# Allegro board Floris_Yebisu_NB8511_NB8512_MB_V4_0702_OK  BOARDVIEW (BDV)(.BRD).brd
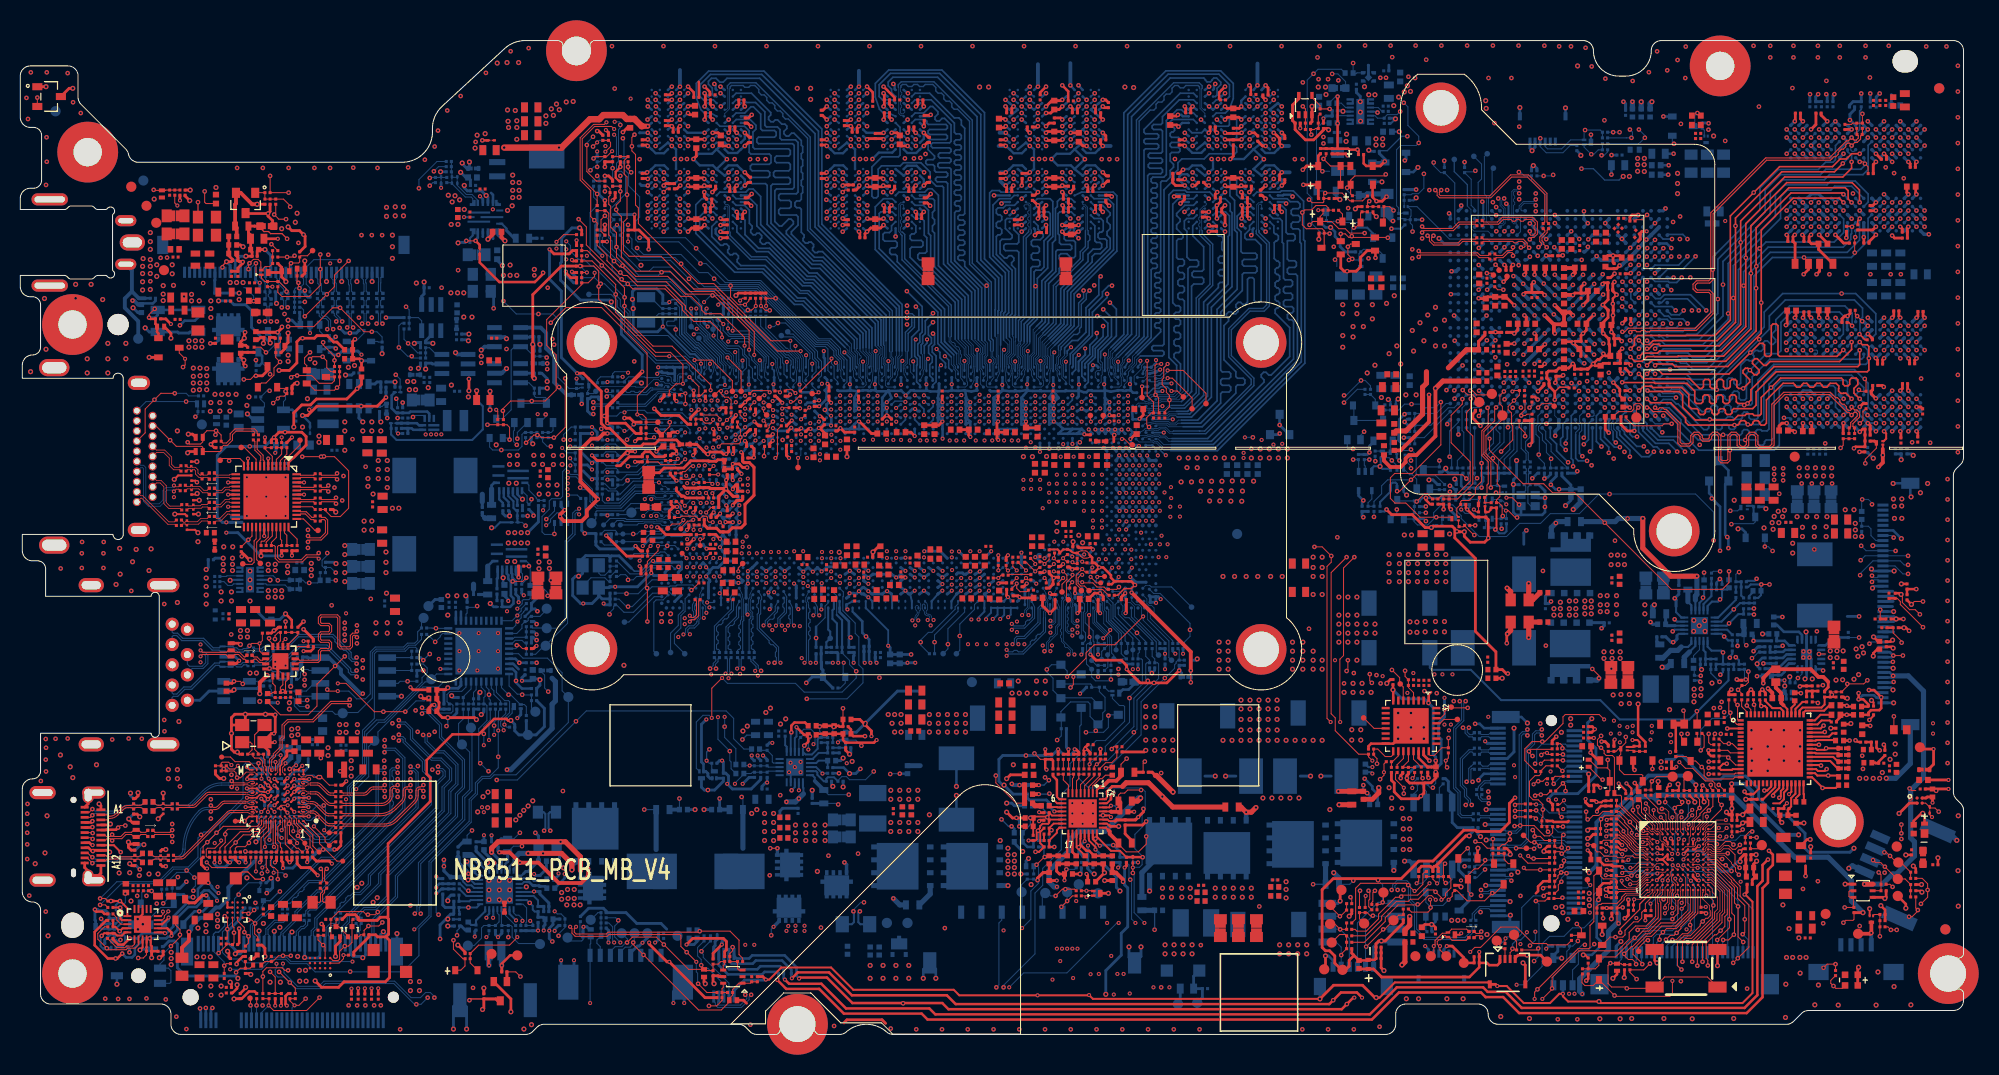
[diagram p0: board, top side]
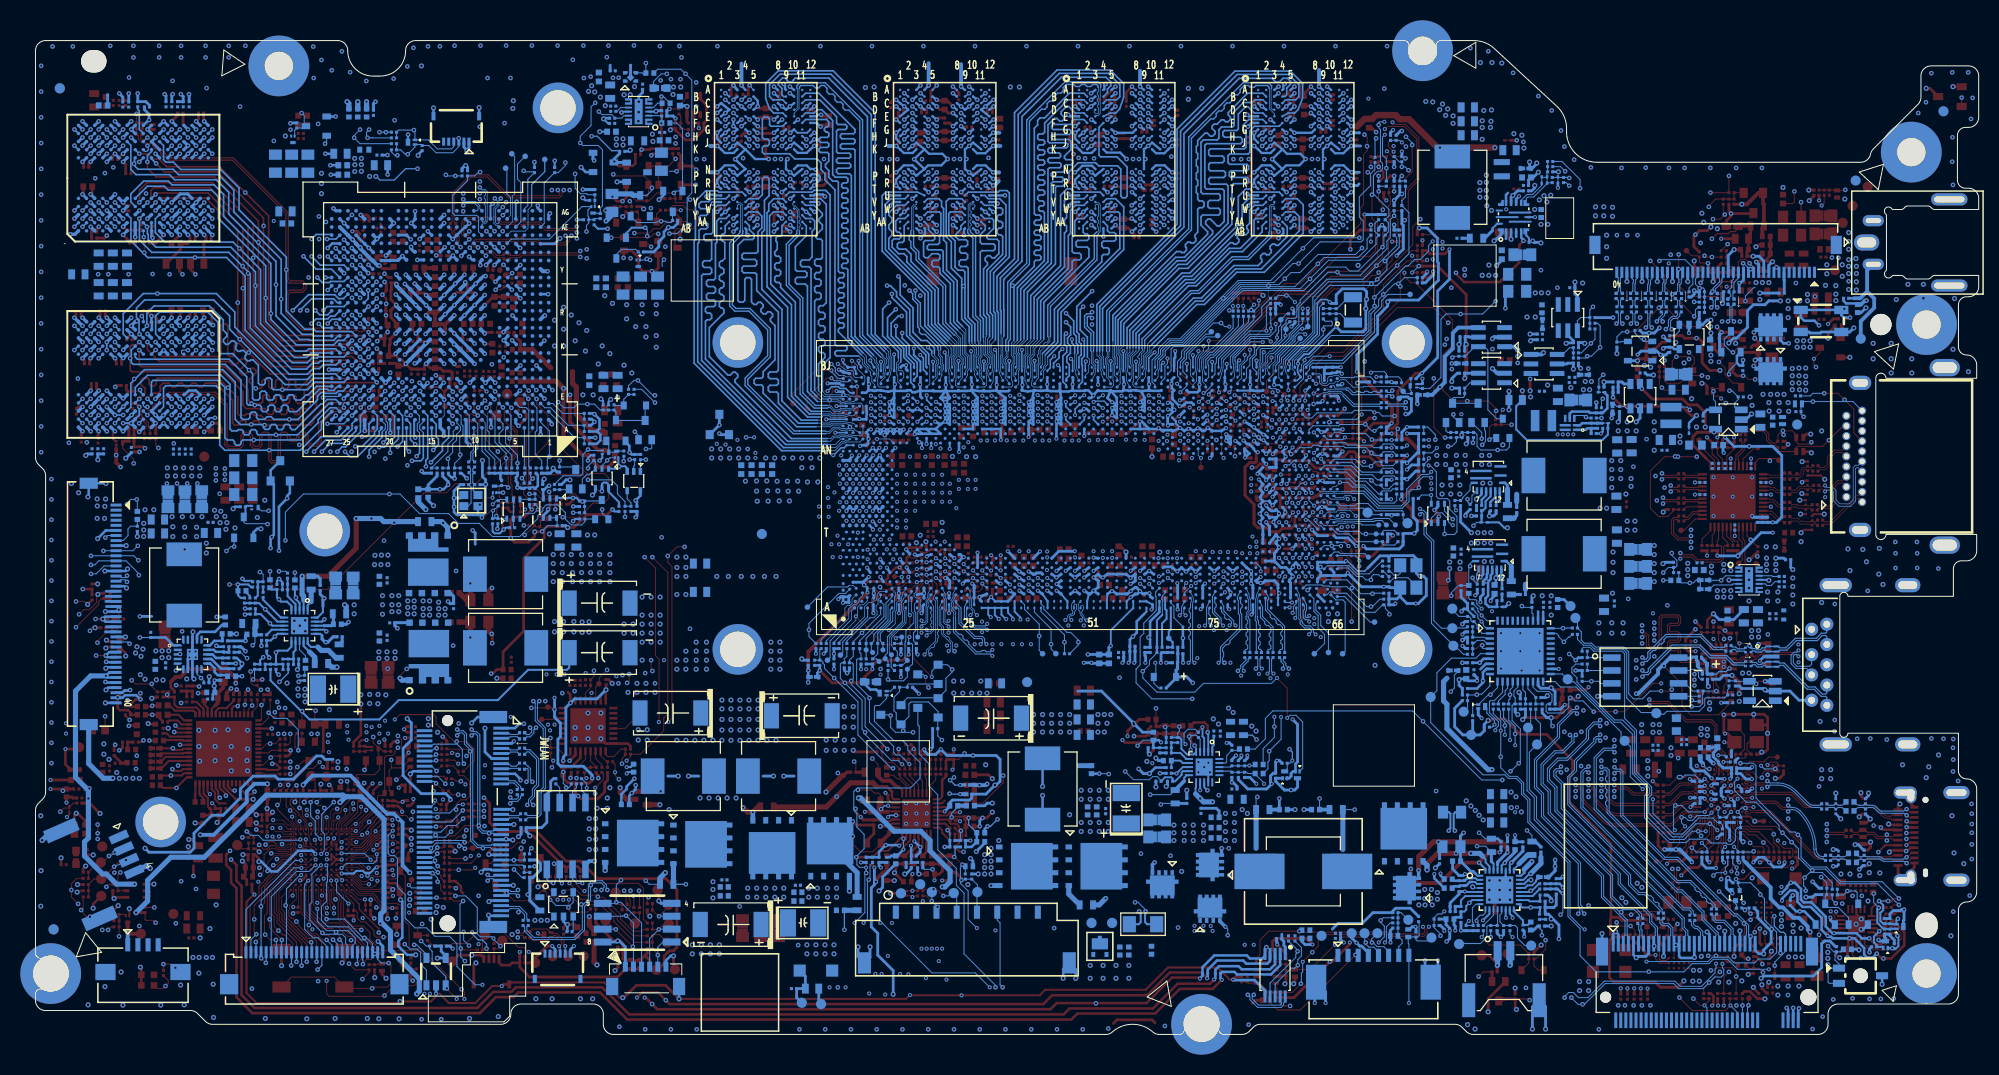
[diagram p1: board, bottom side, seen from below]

Outline 191.65 x 98 mm; copper layers: TOP, GND02, ART03, PWR04, ART05, ART06, GND07, BOTTOM. Coordinates in mm from the lower left corner of the outline.

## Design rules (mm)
constraint set DEFAULT: min track width 0.102
net group 10/10: nets VCC_VCCIN_SENSE_N VCC_VCCIN_SENSE_P
net group BB_TCP0_FLASH_CLK: nets BB_TCP0_FLASH_CLK BB_TCP0_FLASH_CLK_R
net group BB_TCP0_FLASH_CS_N: nets BB_TCP0_FLASH_CS_N BB_TCP0_FLASH_CS_N_R
net group BB_TCP0_FLASH_DI: nets BB_TCP0_FLASH_DI BB_TCP0_FLASH_DI_R
net group BB_TCP0_FLASH_DO: nets BB_TCP0_FLASH_DO BB_TCP0_FLASH_DO_R
net group BC_PROCHOT_N_PD: nets BC_PROCHOT_N_PD SRC_PS_FLT_N
net group BI_GATE: nets BI_GATE N40277712
net group CHG_PSYS: nets CHG_PSYS VR_PSYS
net group CHG_SCL: nets CHG_SCL SM_BAT_CLK
net group CHG_SDA: nets CHG_SDA SM_BAT_DATA
net group CHG_SR: nets CHG_SRN CHG_SRP
net group CNV_WR_CLK_CON_DN: nets CNV_WR_CLK_CON_DN CNV_WR_CLK_DN
net group CNV_WR_CLK_CON_DP: nets CNV_WR_CLK_CON_DP CNV_WR_CLK_DP
net group CNV_WR_D0_CON_DN: nets CNV_WR_D0_CON_DN CNV_WR_LANE0_DN
net group CNV_WR_D0_CON_DP: nets CNV_WR_D0_CON_DP CNV_WR_LANE0_DP
net group CNV_WR_D1_CON_DN: nets CNV_WR_D1_CON_DN CNV_WR_LANE1_DN
net group CNV_WR_D1_CON_DP: nets CNV_WR_D1_CON_DP CNV_WR_LANE1_DP
net group CNV_WT_CLK_DN: nets CNV_WT_CLK_DN CNV_WT_CLK_DN_R
net group CNV_WT_CLK_DP: nets CNV_WT_CLK_DP CNV_WT_CLK_DP_R
net group CNV_WT_LANE0_DN: nets CNV_WT_LANE0_DN CNV_WT_LANE0_DN_R
net group CNV_WT_LANE0_DP: nets CNV_WT_LANE0_DP CNV_WT_LANE0_DP_R
net group CNV_WT_LANE1_DN: nets CNV_WT_LANE1_DN CNV_WT_LANE1_DN_R
net group CNV_WT_LANE1_DP: nets CNV_WT_LANE1_DP CNV_WT_LANE1_DP_R
net group DDI1_HPD: nets DDI1_HPD DDI1_HPD_LV
net group DIFFPAIR333: nets PCIE_RCOMP_N PCIE_RCOMP_P
net group DIFFPAIR531: nets N33196202 N33196257
net group DIFFPAIR532: nets XTAL_IN XTAL_OUT
net group DIFFPAIR534: nets DDI1_DDC_SCL DDI1_DDC_SDA
net group DIFFPAIR541: nets VGA_SMB_CK2 VGA_SMB_DA2
net group DIFFPAIR542: nets SMB_EC_SCLK SMB_EC_SDATA
net group DIFFPAIR545: nets TOUCHPAD_I2C_CLK TOUCHPAD_I2C_SDA
net group DIFFPAIR559: nets FBA_CLK0 FBA_CLK0_N
net group DMIC1_CLK_AUDIO: nets DMIC1_CLK_AUDIO DMIC1_CLK_R
net group DMIC2_CLK_AUDIO: nets DMIC2_CLK_AUDIO DMIC2_CLK_R
net group EC ROM SPI-S-10: nets FLASH_SPI_HOLD_N_EC FLASH_SPI_WP_N_EC
net group EC_IMVP_PWRGD: nets EC_IMVP_PWRGD VR_READY
net group EC_SLP_S0_CS_N: nets EC_SLP_S0_CS_N HDMI_PDB_8409A
net group EDP_AUX_CONN_DN: nets EDP_AUX_C_DN EDP_AUX_CONN_DN
net group EDP_AUX_CONN_DP: nets EDP_AUX_C_DP EDP_AUX_CONN_DP
net group EDP_TX0_CONN_DN: nets EDP_TX0_C_DN EDP_TX0_CONN_DN
net group EDP_TX0_CONN_DP: nets EDP_TX0_C_DP EDP_TX0_CONN_DP
net group EDP_TX1_CONN_DN: nets EDP_TX1_C_DN EDP_TX1_CONN_DN
net group EDP_TX1_CONN_DP: nets EDP_TX1_C_DP EDP_TX1_CONN_DP
net group EDP_TX2_CONN_DN: nets EDP_TX2_C_DN EDP_TX2_CONN_DN
net group EDP_TX2_CONN_DP: nets EDP_TX2_C_DP EDP_TX2_CONN_DP
net group EDP_TX3_CONN_DN: nets EDP_TX3_C_DN EDP_TX3_CONN_DN
net group EDP_TX3_CONN_DP: nets EDP_TX3_C_DP EDP_TX3_CONN_DP
net group FLASH_SPI_IO2: nets FLASH_SPI_IO2 FLASH_SPI_IO2_IC
net group FLASH_SPI_IO3: nets FLASH_SPI_IO3 FLASH_SPI_IO3_IC
net group HDMI_CLK_DN: nets HDMI_CLK_CONN_DN HDMI_CLK_DN
net group HDMI_CLK_DP: nets HDMI_CLK_CONN_DP HDMI_CLK_DP
net group HDMI_DDC_SCL_8409A: nets HDMI_DDC_SCL HDMI_DDC_SCL_8409A
net group HDMI_DDC_SDA_8409A: nets HDMI_DDC_SDA HDMI_DDC_SDA_8409A
net group HDMI_TX0_DN: nets HDMI_TX0_CONN_DN HDMI_TX0_DN
net group HDMI_TX0_DP: nets HDMI_TX0_CONN_DP HDMI_TX0_DP
net group HDMI_TX1_DN: nets HDMI_TX1_CONN_DN HDMI_TX1_DN
net group HDMI_TX1_DP: nets HDMI_TX1_CONN_DP HDMI_TX1_DP
net group HDMI_TX2_DN: nets HDMI_TX2_CONN_DN HDMI_TX2_DN
net group HDMI_TX2_DP: nets HDMI_TX2_CONN_DP HDMI_TX2_DP
net group I2C_PD_SCL: nets I2C_PD_SCL TYPEC_PD_RETIMER_CLK
net group I2C_PD_SDA: nets I2C_PD_SDA TYPEC_PD_RETIMER_DAT
net group MIPI60_CPU_JTAG_TCLK: nets MIPI60_CPU_JTAG_TCLK MIPI60_PCH_JTAGX
net group MIPI60_CPU_JTAG_TDI: nets MIPI60_CPU_JTAG_TDI MIPI60_PCH_JTAG_TDI
net group MIPI60_CPU_JTAG_TDO: nets MIPI60_CPU_JTAG_TDO MIPI60_PCH_JTAG_TDO
net group MIPI60_CPU_JTAG_TMS: nets MIPI60_CPU_JTAG_TMS MIPI60_PCH_JTAG_TMS
net group MIPI60_CPU_JTAG_TRST_N: nets MIPI60_CPU_JTAG_TRST_N MIPI60_PCH_JTAG_TRST_N
net group PSI_VGA: nets PSI_VGA VGA_CORE_PSI
net group PWR_BUTTON_N_KB: nets PWR_BUTTON_N PWR_BUTTON_N_KB
net group SMB_TYPEC_SCLK: nets SMB_TYPEC_SCLK TYPEC_PD_SCLK
net group SMB_TYPEC_SDATA: nets SMB_TYPEC_SDATA TYPEC_PD_SDA
net group SSD_RST_N: nets PLT_RST_N_SSD SSD_RST_N
net group TCP0_ATEST_: nets TCP0_ATEST_N TCP0_ATEST_P
net group TCP0_SBU1: nets TCP0_SBU1 TCP0_SBU1_CONN
net group TCP0_SBU2: nets TCP0_SBU2 TCP0_SBU2_CONN
net group TCP0_TX0_C_DN: nets TCP0_TX0_C_DN TCP0_TX0_DN
net group TCP0_TX0_C_DP: nets TCP0_TX0_C_DP TCP0_TX0_DP
net group TCP0_TX1_C_DN: nets TCP0_TX1_C_DN TCP0_TX1_DN
net group TCP0_TX1_C_DP: nets TCP0_TX1_C_DP TCP0_TX1_DP
net group TCP0_TXRX0_C_DN: nets TCP0_TXRX0_C_DN TCP0_TXRX0_DN
net group TCP0_TXRX0_C_DP: nets TCP0_TXRX0_C_DP TCP0_TXRX0_DP
net group TCP0_TXRX1_C_DN: nets TCP0_TXRX1_C_DN TCP0_TXRX1_DN
net group TCP0_TXRX1_C_DP: nets TCP0_TXRX1_C_DP TCP0_TXRX1_DP
net group TCRCOMP_D: nets TCRCOMP_DN TCRCOMP_DP
net group TYPE-C-85OHM-S-12-S-15: nets TCP0_AUX_DN TCP0_AUX_DP
net group TYPEC_PD_CSN: nets N41385208 TYPEC_PD_CSN
net group TYPEC_PD_CSP: nets N41385128 TYPEC_PD_CSP
net group TYPEC_PD_SOC_CLK: nets TYPEC_PD_SOC_CLK TYPEC_PD_SOC_CLK_R
net group TYPEC_PD_SOC_DAT: nets TYPEC_PD_SOC_DAT TYPEC_PD_SOC_DAT_R
net group USB2_P1_DN_R: nets USB2_P1_DN_R USBP6_DN_CONN
net group USB2_P1_DP_R: nets USB2_P1_DP_R USBP6_DP_CONN
net group USB2_P3_TYPEC_DN: nets USB2_P3_TYPEC_DN USB2_P3_TYPEC_DN_CON
net group USB2_P3_TYPEC_DP: nets USB2_P3_TYPEC_DP USB2_P3_TYPEC_DP_CON
net group VCCIN_AUX_IS: nets VCCIN_AUX_ISN VCCIN_AUX_ISP
net group VCCIN_ISEN1: nets VCCIN_ISEN1N VCCIN_ISEN1P
net group VCCIN_ISEN2: nets VCCIN_ISEN2N VCCIN_ISEN2P
net group VCCIN_VIDSCK: nets VCCIN_VIDSCK VCCIN_VIDSCK_R
net group VCCIN_VIDSOUT: nets VCCIN_VIDSOUT VCCIN_VIDSOUT_R
net group VCCSENSE_VGA: nets VCCSENSE_VGA VGA_CORE_VSNS
net group VSSSENSE_VGA: nets VGA_CORE_RGND VSSSENSE_VGA
net group 3P3VA_EN: nets 3P3VA_EN EC_OVT_N EC_WRST_N N39502644 N39574885
net group +VCC3V3_SX_TCP1: nets N40898959
net group BB_TCP0_RESET_N: nets BB_TCP0_RESET_N SLP_S5_N TCP0_RESET_N
net group BB_TCP1_LS_EN: nets BB_TCP1_LS_EN BB_TCP1_LS_EN_R UART_TX_P1
net group CLK-S-15: nets PCIE_SSD_CLKREQ1 PCIE_WLAN_CLK_REQ_N PCIE_WLAN_CLK_REQ_N_C
net group DDI-85OHM-S-12: nets DDI1_TX0_DN DDI1_TX0_DP DDI1_TX1_DN DDI1_TX1_DP DDI1_TX2_DN DDI1_TX2_DP DDI1_TX3_DN DDI1_TX3_DP HDMI_CLK_LV_DN HDMI_CLK_LV_DP HDMI_TX0_LV_DN HDMI_TX0_LV_DP HDMI_TX1_LV_DN HDMI_TX1_LV_DP HDMI_TX2_LV_DN HDMI_TX2_LV_DP
net group DDR4-CLKA-75OHM-S-12-S-20: nets M_A_CK_DDR0_DN M_A_CK_DDR0_DP M_A_CK_DDR1_DN M_A_CK_DDR1_DP
net group DDR4-CLKB-75OHM-S-12-S-20: nets M_B_CK_DDR0_DN M_B_CK_DDR0_DP M_B_CK_DDR1_DN M_B_CK_DDR1_DP
net group DDR4-CMDA-40OHM-S-10-S-20: nets M_A_LP4_CAA0 M_A_LP4_CAA1 M_A_LP4_CAA2 M_A_LP4_CAA3 M_A_LP4_CAA4 M_A_LP4_CAA5 M_A_LP4_CAB0 M_A_LP4_CAB1 M_A_LP4_CAB2 M_A_LP4_CAB3 M_A_LP4_CAB4 M_A_LP4_CAB5 M_A_LP4_CKE_A0 M_A_LP4_CKE_A1 M_A_LP4_CKE_B0 M_A_LP4_CKE_B1 M_A_LP4_CS_A_R0_N M_A_LP4_CS_A_R1_N M_A_LP4_CS_B_R0_N M_A_LP4_CS_B_R1_N
net group DDR4-CMDB-40OHM-S-10-S-15: nets M_B_LP4_CAA0 M_B_LP4_CAA1 M_B_LP4_CAA2 M_B_LP4_CAA3 M_B_LP4_CAA4 M_B_LP4_CAA5 M_B_LP4_CAB0 M_B_LP4_CAB1 M_B_LP4_CAB2 M_B_LP4_CAB3 M_B_LP4_CAB4 M_B_LP4_CAB5 M_B_LP4_CKE_A0 M_B_LP4_CKE_A1 M_B_LP4_CKE_B0 M_B_LP4_CKE_B1 M_B_LP4_CS_A_R0_N M_B_LP4_CS_A_R1_N M_B_LP4_CS_B_R0_N M_B_LP4_CS_B_R1_N
net group DDR4-DATA0-40OHM-S-6-S-15: nets M_A_DQ_0[0] M_A_DQ_0[1] M_A_DQ_0[2] M_A_DQ_0[3] M_A_DQ_0[4] M_A_DQ_0[5] M_A_DQ_0[6] M_A_DQ_0[7] M_A_DQS_0_DN M_A_DQS_0_DP
net group DDR4-DATA1-40OHM-S-6-S-15: nets M_A_DQ_1[0] M_A_DQ_1[1] M_A_DQ_1[2] M_A_DQ_1[3] M_A_DQ_1[4] M_A_DQ_1[5] M_A_DQ_1[6] M_A_DQ_1[7] M_A_DQS_1_DN M_A_DQS_1_DP
net group DDR4-DATA2-40OHM-S-6-S-15: nets M_A_DQ_2[0] M_A_DQ_2[1] M_A_DQ_2[2] M_A_DQ_2[3] M_A_DQ_2[4] M_A_DQ_2[5] M_A_DQ_2[6] M_A_DQ_2[7] M_A_DQS_2_DN M_A_DQS_2_DP
net group DDR4-DATA3-40OHM-S-6-S-15: nets M_A_DQ_3[0] M_A_DQ_3[1] M_A_DQ_3[2] M_A_DQ_3[3] M_A_DQ_3[4] M_A_DQ_3[5] M_A_DQ_3[6] M_A_DQ_3[7] M_A_DQS_3_DN M_A_DQS_3_DP
net group DDR4-DATA4-40OHM-S-6-S-15: nets M_A_DQ_4[0] M_A_DQ_4[1] M_A_DQ_4[2] M_A_DQ_4[3] M_A_DQ_4[4] M_A_DQ_4[5] M_A_DQ_4[6] M_A_DQ_4[7] M_A_DQS_4_DN M_A_DQS_4_DP
net group DDR4-DATA5-40OHM-S-6-S-15: nets M_A_DQ_5[0] M_A_DQ_5[1] M_A_DQ_5[2] M_A_DQ_5[3] M_A_DQ_5[4] M_A_DQ_5[5] M_A_DQ_5[6] M_A_DQ_5[7] M_A_DQS_5_DN M_A_DQS_5_DP
net group DDR4-DATA6-40OHM-S-6-S-15: nets M_A_DQ_6[0] M_A_DQ_6[1] M_A_DQ_6[2] M_A_DQ_6[3] M_A_DQ_6[4] M_A_DQ_6[5] M_A_DQ_6[6] M_A_DQ_6[7] M_A_DQS_6_DN M_A_DQS_6_DP
net group DDR4-DATA7-40OHM-S-6-S-15: nets M_A_DQ_7[0] M_A_DQ_7[1] M_A_DQ_7[2] M_A_DQ_7[3] M_A_DQ_7[4] M_A_DQ_7[5] M_A_DQ_7[6] M_A_DQ_7[7] M_A_DQS_7_DN M_A_DQS_7_DP
net group DDR4-DATAB0-40OHM-S-6-S-15: nets M_B_DQ_0[0] M_B_DQ_0[1] M_B_DQ_0[2] M_B_DQ_0[3] M_B_DQ_0[4] M_B_DQ_0[5] M_B_DQ_0[6] M_B_DQ_0[7] M_B_DQS_0_DN M_B_DQS_0_DP
net group DDR4-DATAB1-40OHM-S-6-S-15: nets M_B_DQ_1[0] M_B_DQ_1[1] M_B_DQ_1[2] M_B_DQ_1[3] M_B_DQ_1[4] M_B_DQ_1[5] M_B_DQ_1[6] M_B_DQ_1[7] M_B_DQS_1_DN M_B_DQS_1_DP
net group DDR4-DATAB2-40OHM-S-6-S-15: nets M_B_DQ_2[0] M_B_DQ_2[1] M_B_DQ_2[2] M_B_DQ_2[3] M_B_DQ_2[4] M_B_DQ_2[5] M_B_DQ_2[6] M_B_DQ_2[7] M_B_DQS_2_DN M_B_DQS_2_DP
net group DDR4-DATAB3-40OHM-S-6-S-15: nets M_B_DQ_3[0] M_B_DQ_3[1] M_B_DQ_3[2] M_B_DQ_3[3] M_B_DQ_3[4] M_B_DQ_3[5] M_B_DQ_3[6] M_B_DQ_3[7] M_B_DQS_3_DN M_B_DQS_3_DP
net group DDR4-DATAB4-40OHM-S-6-S-15: nets M_B_DQ_4[0] M_B_DQ_4[1] M_B_DQ_4[2] M_B_DQ_4[3] M_B_DQ_4[4] M_B_DQ_4[5] M_B_DQ_4[6] M_B_DQ_4[7] M_B_DQS_4_DN M_B_DQS_4_DP
net group DDR4-DATAB5-40OHM-S-6-S-15: nets M_B_DQ_5[0] M_B_DQ_5[1] M_B_DQ_5[2] M_B_DQ_5[3] M_B_DQ_5[4] M_B_DQ_5[5] M_B_DQ_5[6] M_B_DQ_5[7] M_B_DQS_5_DN M_B_DQS_5_DP
net group DDR4-DATAB6-40OHM-S-6-S-15: nets M_B_DQ_6[0] M_B_DQ_6[1] M_B_DQ_6[2] M_B_DQ_6[3] M_B_DQ_6[4] M_B_DQ_6[5] M_B_DQ_6[6] M_B_DQ_6[7] M_B_DQS_6_DN M_B_DQS_6_DP
net group DDR4-DATAB7-40OHM-S-6-S-15: nets M_B_DQ_7[0] M_B_DQ_7[1] M_B_DQ_7[2] M_B_DQ_7[3] M_B_DQ_7[4] M_B_DQ_7[5] M_B_DQ_7[6] M_B_DQ_7[7] M_B_DQS_7_DN M_B_DQS_7_DP
net group DDR-FBA_WCK-80OHM-S-12: nets FBA_WCK01 FBA_WCK01_N FBA_WCK23 FBA_WCK23_N FBA_WCK45 FBA_WCK45_N FBA_WCK67 FBA_WCK67_N
net group DIFF-I2C: nets DMIC1_CLK DMIC1_DATA DMIC1_DATA_AUDIO N26347975 N26347977 PCH_DMIC1_CLK0 PCH_DMIC1_DATA0 PCH_SMB1_CLK PCH_SMB1_DATA SM_BATT_SCL SM_BATT_SDA TOUCHPAD_I2C_CLK_C TOUCHPAD_I2C_SDA_C
net group EC SPI-S-10: nets ESPI_CLK ESPI_CLK_EC ESPI_CS_N ESPI_IO0 ESPI_IO0_EC ESPI_IO1 ESPI_IO1_EC ESPI_IO2 ESPI_IO2_EC ESPI_IO3 ESPI_IO3_EC ESPI_RESET
net group EC_FLASH_SPI_CLK: nets EC_FLASH_SPI_CLK FLASH_SPI_CLK FLASH_SPI_CLK_EC FLASH_SPI_CLK_IC
net group EC_FLASH_SPI_CS0_N: nets EC_FLASH_SPI_CS0_N FLASH_SPI_CS0_N FLASH_SPI_CS0_N_EC FLASH_SPI_CS0_N_IC
net group EC_FLASH_SPI_MISO: nets EC_FLASH_SPI_MISO FLASH_SPI_MISO FLASH_SPI_MISO_EC FLASH_SPI_MISO_IC
net group EC_FLASH_SPI_MOSI: nets EC_FLASH_SPI_MOSI FLASH_SPI_MOSI FLASH_SPI_MOSI_EC FLASH_SPI_MOSI_IC
net group EC_SLP_SX_N: nets EC_SLP_SX_N N40993990 N42165106
net group EDP-85OHM-S-12: nets EDP_AUX_SOC_DN EDP_AUX_SOC_DP EDP_TX0_SOC_DN EDP_TX0_SOC_DP EDP_TX1_SOC_DN EDP_TX1_SOC_DP EDP_TX2_SOC_DN EDP_TX2_SOC_DP EDP_TX3_SOC_DN EDP_TX3_SOC_DP
net group GDRR5_ADD_H-40OHM-S-13.5: nets FBA_A0_A10_H FBA_A1_A9_H FBA_A2_BA0_H FBA_A3_BA3_H FBA_A4_BA2_H FBA_A5_BA1_H FBA_A6_A11_H FBA_A7_A8_H FBA_A12_RFU_H
net group GDRR5_ADD_L-40OHM-S-13.5: nets FBA_A0_A10_L FBA_A1_A9_L FBA_A3_BA3_L FBA_A4_BA2_L FBA_A5_BA1_L FBA_A6_A11_L FBA_A7_A8_L FBA_A12_RFU_L
net group GDRR5_CMD_H-40OHM-S-13.5: nets FBA_ABI_H FBA_CAS_H FBA_CS_H FBA_RAS_H FBA_WE_H
net group GDRR5_CMD_L-40OHM-S-13.5: nets FBA_ABI_L FBA_CAS_L FBA_CS_L FBA_RAS_L FBA_WE_L
net group GDRR5_CONTROL-40OHM-S-13.5: nets FBA_RST_L
net group HDMI-85OHM-S-12: nets HDMI_CLK_CONN_DN_R HDMI_CLK_CONN_DP_R HDMI_TX0_CONN_DN_R HDMI_TX0_CONN_DP_R HDMI_TX1_CONN_DN_R HDMI_TX1_CONN_DP_R HDMI_TX2_CONN_DN_R HDMI_TX2_CONN_DP_R
net group PCIE-85OHM-S-12: nets PCIE13_CRX_DTX_N PCIE13_CRX_DTX_P PCIE13_CTX_DRX_N PCIE13_CTX_DRX_N_C PCIE13_CTX_DRX_P PCIE13_CTX_DRX_P_C PCIE14_CRX_DTX_N PCIE14_CRX_DTX_P PCIE14_CTX_DRX_N PCIE14_CTX_DRX_N_C PCIE14_CTX_DRX_P PCIE14_CTX_DRX_P_C PCIE15_CRX_DTX_N PCIE15_CRX_DTX_P PCIE15_CTX_DRX_N PCIE15_CTX_DRX_N_C PCIE15_CTX_DRX_P PCIE15_CTX_DRX_P_C PCIE16_SATA_CRX_DTX_N PCIE16_SATA_CRX_DTX_P PCIE16_SATA_CTX_DRX_N PCIE16_SATA_CTX_DRX_N_C PCIE16_SATA_CTX_DRX_P PCIE16_SATA_CTX_DRX_P_C PCIE_CRX_C_GTX_N0 PCIE_CRX_C_GTX_N1 PCIE_CRX_C_GTX_N2 PCIE_CRX_C_GTX_N3 PCIE_CRX_C_GTX_P0 PCIE_CRX_C_GTX_P1 PCIE_CRX_C_GTX_P2 PCIE_CRX_C_GTX_P3 PCIE_CRX_GTX_N0 PCIE_CRX_GTX_N1 PCIE_CRX_GTX_N2 PCIE_CRX_GTX_N3 PCIE_CRX_GTX_P0 PCIE_CRX_GTX_P1 PCIE_CRX_GTX_P2 PCIE_CRX_GTX_P3 PCIE_CTX_GRX_N0 PCIE_CTX_GRX_N0_C PCIE_CTX_GRX_N1 PCIE_CTX_GRX_N1_C PCIE_CTX_GRX_N2 PCIE_CTX_GRX_N2_C PCIE_CTX_GRX_N3 PCIE_CTX_GRX_N3_C PCIE_CTX_GRX_P0 PCIE_CTX_GRX_P0_C PCIE_CTX_GRX_P1 PCIE_CTX_GRX_P1_C PCIE_CTX_GRX_P2 PCIE_CTX_GRX_P2_C PCIE_CTX_GRX_P3 PCIE_CTX_GRX_P3_C PCIE_WLAN_RX_DN PCIE_WLAN_RX_DP PCIE_WLAN_TX_DN PCIE_WLAN_TX_DN_C PCIE_WLAN_TX_DP PCIE_WLAN_TX_DP_C
net group PCIE-CLK-85OHM-S-12-S-15: nets PCIE_REFCLK_GFX_DN PCIE_REFCLK_GFX_DP PCIE_REFCLK_SSD_DN PCIE_REFCLK_SSD_DP PCIE_REFCLK_WLAN_DN PCIE_REFCLK_WLAN_DP
net group PLT_RST_N: nets PLT_RST_N TCP_RETIMER_PERST_N TCP_RETIMER_PERST_N_R
net group PWR: nets 1V8MAINEN_33 +V1P8_AON_EN_N +V3P3_CAM_CONN +V3P3_MIC +V3P3A_SPI_FLASH +V3P3A_VSYS_PD +VBUS_WC +VCC0P9_LVR_TCP1 +VCC3V3A_S0_TCP1 +VCCDSW_1P05 +VCCRTC CHG_COMP1 CHG_COMP1_R CHG_ILIM_HIZ CHG_REGN CHG_SNB2 CHG_VBUS CHG_VDDA CPU_POPI_RCOMP GPPC_B2_VRALERT_N N28124431 N29343591 N32026426 N32026428 N32028000 N32264097 N33504961 N38294628 N38297214 N39869300 N40407372 N40407375 N41030628 N41496684 V1P8A_EN V1P8A_FB V1P8A_FB_R V5P0A_BST_R V5P0A_FB V5P0A_FF V5P0A_FF_R V5P0A_LDO V5P0A_VCC VCCIN_AUX_VCCSENSE VCCIN_AUX_VSSSENSE VCCIN_BOOT1 VCCIN_BOOT1_R VCCIN_BOOT2 VCCIN_BOOT2_R VCCIN_LGATE1 VCCIN_LGATE2 VCCIN_PH1_SNUB VCCIN_PVCC VCCIN_UGATE1 VCCIN_UGATE1_R VCCIN_UGATE2 VCCIN_VREF VGA_CORE_UG1
net group RETIMER_FORCE_PWR: nets RETIMER_FORCE_PWR TC_RETIMER_FORCE_PWR UART_RX_P1
net group RT_TCP0_I2C0_SCL: nets RT_TCP0_I2C0_SCL SMBUS_CLK0 TCP_SMBUS_SCL
net group RT_TCP0_I2C0_SDA: nets RT_TCP0_I2C0_SDA SMBUS_DAT0 TCP_SMBUS_SDA
net group S-10-S-15: nets CNV_BRI_DT CNV_BRI_DT_SOC CNV_BRI_RSP CNV_BRI_RSP_SOC CNV_RGI_DT CNV_RGI_DT_SOC CNV_RGI_RSP CNV_RGI_RSP_SOC
net group S-12: nets CATERR_SOC_N CPU_PROCHOT_EC DSW_PWROK H_VCCST_PWRGD N38298094 PCH_PWROK PECI_EC PECI_SOC PLT_RST_SOC_N PM_SYSRST_N PROCHOT_EC_N PROCHOT_SOC_N PROCPWRGD RSMRST_N_EC SYS_PWROK TBT_LSX0_RXD TBT_LSX0_TXD THERMTRIP_SOC_N VCCST_OVERRIDE VCCSTPWRGOOD_TCSS
net group SNK_PS_ACK: nets SNK_PS_ACK SRC_PS_FO SRC_PS_FO_OVP_TRIP
net group TCP0_CC1_CONN: nets N40901169 TCP0_CC1_CONN TCP0_CC1_PD
net group TCP0_CC2_CONN: nets N40901167 TCP0_CC2_CONN TCP0_CC2_PD
net group TCP0_RT_TX0_DN: nets TCP0_RT_TX0_DN TCP0_RT_TX0_DN_C TCP0_RT_TX0_DN_CONN
net group TCP0_RT_TX0_DP: nets TCP0_RT_TX0_DP TCP0_RT_TX0_DP_C TCP0_RT_TX0_DP_CONN
net group TCP0_RT_TX1_DN: nets TCP0_RT_TX1_DN TCP0_RT_TX1_DN_C TCP0_RT_TX1_DN_CONN
net group TCP0_RT_TX1_DP: nets TCP0_RT_TX1_DP TCP0_RT_TX1_DP_C TCP0_RT_TX1_DP_CONN
net group TCP0_RT_TXRX0_DN: nets TCP0_RT_TXRX0_DN TCP0_RT_TXRX0_DN_C TCP0_RT_TXRX0_DN_CONN
net group TCP0_RT_TXRX0_DP: nets TCP0_RT_TXRX0_DP TCP0_RT_TXRX0_DP_C TCP0_RT_TXRX0_DP_CONN
net group TCP0_RT_TXRX1_DN: nets TCP0_RT_TXRX1_DN TCP0_RT_TXRX1_DN_C TCP0_RT_TXRX1_DN_CONN
net group TCP0_RT_TXRX1_DP: nets TCP0_RT_TXRX1_DP TCP0_RT_TXRX1_DP_C TCP0_RT_TXRX1_DP_CONN
net group TPM SPI: nets FLASH_SPI_CLK_TPM FLASH_SPI_CS2_N FLASH_SPI_CS2_N_TPM FLASH_SPI_MISO_TPM FLASH_SPI_MOSI_TPM
net group USB2-85OHM-S-12: nets CAM_USB_N_CONN_R CAM_USB_P_CONN_R USB2_P1_DN USB2_P1_DP USB2_P4_DN USB2_P4_DP USB2_P5_DN_FP USB2_P5_DP_FP USB2_P5_FP_DN USB2_P5_FP_DP USB2_P9_TS_DN USB2_P9_TS_DN_R USB2_P9_TS_DP USB2_P9_TS_DP_R USB2_P10_BT_DN USB2_P10_BT_DN_WIFI USB2_P10_BT_DP USB2_P10_BT_DP_WIFI USB_P7_CAM_N USB_P7_CAM_P
net group USB3-80MIL-18-S-20: nets USB3_P1_RX_DN USB3_P1_RX_DP USB3_P1_TX_DN USB3_P1_TX_DN_C USB3_P1_TX_DP USB3_P1_TX_DP_C USB3_RXN1_R USB3_RXP1_R USB3_TXN1_R USB3_TXP1_R
net group VCCIN_VIDALERT_N: nets VCCIN_VIDALERT_N VCCIN_VIDALERT_N_R VR_SVID_ALERT_N

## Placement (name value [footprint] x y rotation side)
+1.35VGS1  C40_1  [CMP_40]  175 56.97 0 top
+V1P8SX  40MIL  [CMP_40]  187.35 28.32 0 top
+V5P0SX_HDMI_F  C40_1  [CMP_40]  17.91 60.14 180 bottom
+VCCIN1  C40_1  [CMP_40]  120.01 49.35 90 bottom
+VCCIN_AUX1  C40_1  [CMP_40]  93.85 34.74 180 bottom
C8  C0201C0G101J250NTA+C0201C0G101J250NJA~~GRM0335C1E101JD01D~~CC0201JRNPO8BN101  [C0201]  14.73 83 270 top
C9  C0402X5R475M6R3NTC~~JMK105BBJ475MV-F+JDK105ABJ475MV~~CC0402MRX5R5BB475~~CL05A475MQ5NRNC~~GRM155R60J475ME87D  [C0402_0D65]  138.22 10.13 270 top
C10  C0201X5R104M6R3NTA~~0201X104M6R3NT  [C0201]  139.57 10.16 90 top
CA8  C0402X5R106M6R3NTC~~CL05A106MQ5NUNC~~GRM155R60J106ME44~~JMK105CBJ106MV-F  [C0402_0D8]  173.23 33.17 180 top
CA11  CL10A226MQ8NRNC~~GRM188R60J226MEA0D~~JDK107BBJ226MA-T~~CC0603MRX5R5BB226  [C0603_L]  175.61 17.96 90 top
CA12  C0201X5R104K6R3NTA+C0201X5R104K6R3NJA~~GRM033R60J104KE19D~~CC0201KRX5R5BB104  [C0201]  176.58 17.65 90 top
CA13  CL10A226MQ8NRNC~~GRM188R60J226MEA0D~~JDK107BBJ226MA-T~~CC0603MRX5R5BB226  [C0603_L]  171.24 22.27 180 top
CA14  C0201X5R104K6R3NTA+C0201X5R104K6R3NJA~~GRM033R60J104KE19D~~CC0201KRX5R5BB104  [C0201]  171.55 23.19 180 top
CA15  C0201X5R104K6R3NTA+C0201X5R104K6R3NJA~~GRM033R60J104KE19D~~CC0201KRX5R5BB104  [C0201]  176.17 33.04 90 top
CA16  C0201C0G101J250NTA+C0201C0G101J250NJA~~GRM0335C1E101JD01D~~CC0201JRNPO8BN101  [C0201]  176.73 34.11 90 top
CA17  C0603X5R106M6R3NTK~~CL10A106MQ8NNNC~~GRM188R60J106ME47D~~JMK107BJ106MA-T  [C0603_L]  171.24 20.95 180 top
CA18  C0201X5R104K6R3NTA+C0201X5R104K6R3NJA~~GRM033R60J104KE19D~~CC0201KRX5R5BB104  [C0201]  173.12 22.27 0 top
CA23  C0201C0G2R0C250NTA~~GRM0335C1E2R0CD01D~~CC0201CRNPO9BN2R0  [C0201]  169.8 34.67 90 top
CA24  C0201C0G100J250NTA~~GRM0335C1E100JA01D~~CC0201JRNPO8BN100  [C0201]  170.38 33.25 90 top
CA25  C0201C0G100J250NTA~~GRM0335C1E100JA01D~~CC0201JRNPO8BN100  [C0201]  169.11 33.25 90 top
CA26  C0201C0G100J250NTA~~GRM0335C1E100JA01D~~CC0201JRNPO8BN100  [C0201]  167.28 27.45 180 top
CA27  C0402X5R106M6R3NTC~~CL05A106MQ5NUNC~~GRM155R60J106ME44~~JMK105CBJ106MV-F  [C0402_0D8]  166.42 31.11 90 top
CA28  C0201X5R104K6R3NTA+C0201X5R104K6R3NJA~~GRM033R60J104KE19D~~CC0201KRX5R5BB104  [C0201]  170.69 23.44 270 top
CA31  CC0201JRNPO9BN220~~C0201C0G220J500NTA  [C0201]  170.94 33.25 90 top
CA32  C0402X5R106M6R3NTC~~CL05A106MQ5NUNC~~GRM155R60J106ME44~~JMK105CBJ106MV-F  [C0402_0D8]  181.66 30.05 90 top
CA34  GRM155R60J225KE95~~CL05A225KQ5NNNC  [C0402]  167.33 31.11 90 top
CA35  C0201X5R104K6R3NTA+C0201X5R104K6R3NJA~~GRM033R60J104KE19D~~CC0201KRX5R5BB104  [C0201]  184.35 26.24 270 top
CA36  C0201X5R104K6R3NTA+C0201X5R104K6R3NJA~~GRM033R60J104KE19D~~CC0201KRX5R5BB104  [C0201]  174.42 33.07 180 bottom
CA37  C0201X5R104K6R3NTA+C0201X5R104K6R3NJA~~GRM033R60J104KE19D~~CC0201KRX5R5BB104  [C0201]  184.02 38.48 90 top
CA38  C0201X7R221K500NTA~~GRM033R71H221KA12D~~CC0201KRX7R9BB221  [C0201]  184.3 43.25 90 top
CA56  GRM155R60J225KE95~~CL05A225KQ5NNNC  [C0402]  179.83 30.2 90 top
CA57  C0201X5R104K6R3NTA+C0201X5R104K6R3NJA~~GRM033R60J104KE19D~~CC0201KRX5R5BB104  [C0201]  179.07 29.94 90 top
CA58  GRM155R60J225KE95~~CL05A225KQ5NNNC  [C0402]  179.73 25.4 0 top
CA59  GRM155R60J225KE95~~CL05A225KQ5NNNC  [C0402]  179.73 24.58 0 top
CA60  GRM155R60J225KE95~~CL05A225KQ5NNNC  [C0402]  175.51 22.93 0 top
CA61  GRM155R60J225KE95~~CL05A225KQ5NNNC  [C0402]  173.94 21.61 180 top
CA62  C0201X5R104K6R3NTA+C0201X5R104K6R3NJA~~GRM033R60J104KE19D~~CC0201KRX5R5BB104  [C0201]  174.19 22.27 180 top
CA63  C0201C0G100J250NTA~~GRM0335C1E100JA01D~~CC0201JRNPO8BN100  [C0201]  167.28 28.01 180 top
CA64  C0201X5R104K6R3NTA+C0201X5R104K6R3NJA~~GRM033R60J104KE19D~~CC0201KRX5R5BB104  [C0201]  168.5 33.25 90 top
CA65  C0201X5R104K6R3NTA+C0201X5R104K6R3NJA~~GRM033R60J104KE19D~~CC0201KRX5R5BB104  [C0201]  171.55 33.25 90 top
CA66  C0201X5R104K6R3NTA+C0201X5R104K6R3NJA~~GRM033R60J104KE19D~~CC0201KRX5R5BB104  [C0201]  168.04 31.01 90 top
CA67  C0201X5R104K6R3NTA+C0201X5R104K6R3NJA~~GRM033R60J104KE19D~~CC0201KRX5R5BB104  [C0201]  167.28 26.29 180 top
CA68  GRM155R60J225KE95~~CL05A225KQ5NNNC  [C0402]  175 33.3 90 top
CA69  GRM155R60J225KE95~~CL05A225KQ5NNNC  [C0402]  179.42 28.98 0 top
CA70  GRM155R60J225KE95~~CL05A225KQ5NNNC  [C0402]  182.22 26.79 180 top
CA71  GRM155R60J225KE95~~CL05A225KQ5NNNC  [C0402]  182.17 28.09 180 top
CA72  C0402X5R106M6R3NTC~~CL05A106MQ5NUNC~~GRM155R60J106ME44~~JMK105CBJ106MV-F  [C0402_0D8]  179.07 31.52 0 top
CA73  C0402X5R106M6R3NTC~~CL05A106MQ5NUNC~~GRM155R60J106ME44~~JMK105CBJ106MV-F  [C0402_0D8]  179.07 32.46 0 top
CA74  C0201X5R104K6R3NTA+C0201X5R104K6R3NJA~~GRM033R60J104KE19D~~CC0201KRX5R5BB104  [C0201]  179.63 33.53 270 top
CA75  C0201X7R221K500NTA~~GRM033R71H221KA12D~~CC0201KRX7R9BB221  [C0201]  186.08 44.17 90 top
CA76  C0201X7R221K500NTA~~GRM033R71H221KA12D~~CC0201KRX7R9BB221  [C0201]  183.18 40.97 180 top
CA77  C0201X7R221K500NTA~~GRM033R71H221KA12D~~CC0201KRX7R9BB221  [C0201]  183.84 40.1 180 top
CA78  C0201C0G101J250NTA+C0201C0G101J250NJA~~GRM0335C1E101JD01D~~CC0201JRNPO8BN101  [C0201]  182.52 31.52 0 top
CA79  C0201C0G101J250NTA+C0201C0G101J250NJA~~GRM0335C1E101JD01D~~CC0201JRNPO8BN101  [C0201]  182.52 32.38 0 top
CA80  C0201X7R472K100NTA+C0201X7R472K100NJA~~GRM033R71A472KA01D~~CC0201KRX7R6BB472  [C0201]  183.54 26.74 0 top
CA81  C0201X7R472K100NTA+C0201X7R472K100NJA~~GRM033R71A472KA01D~~CC0201KRX7R6BB472  [C0201]  181.76 28.83 180 top
CA82  C0201X5R104K6R3NTA+C0201X5R104K6R3NJA~~GRM033R60J104KE19D~~CC0201KRX5R5BB104  [C0201]  183.77 14.17 0 top
CB32  C0201X5R105M6R3NTX~~CL03A105MQ3CSNH~~GRM033R60J105MEA2D~~JMK063ABJ105MP+JDK063ABJ105MP~~CC0201MRX5R5BB105  [C0201_0D4]  19.99 41.24 90 bottom
CB33  C0201X5R104M6R3NTA~~0201X104M6R3NT  [C0201]  20.63 41.24 90 bottom
CB34  C0402X5R106M6R3NTC~~CL05A106MQ5NUNC~~GRM155R60J106ME44~~JMK105CBJ106MV-F  [C0402_0D8]  27.43 33.3 270 top
CB35  C0201X5R104M6R3NTA~~0201X104M6R3NT  [C0201]  26.67 33.5 270 top
CB36  C0201X5R104M6R3NTA~~0201X104M6R3NT  [C0201]  27.38 39.9 90 top
CB38  C0201X5R104M6R3NTA~~0201X104M6R3NT  [C0201]  25.14 33.47 90 top
CB390  CL10A226MQ8NRNC~~GRM188R60J226MEA0D~~JDK107BBJ226MA-T~~CC0603MRX5R5BB226  [C0603_L]  23.17 41.24 90 top
CB392  CC0201KRX5R7BB104~~C0201X5R104M160NTA  [C0201]  24.69 37.79 180 bottom
CB393  CL10A226MQ8NRNC~~GRM188R60J226MEA0D~~JDK107BBJ226MA-T~~CC0603MRX5R5BB226  [C0603_L]  21.77 41.24 90 top
CB394  CC0201KRX5R7BB104~~C0201X5R104M160NTA  [C0201]  24.69 38.35 180 bottom
CB395  C0201X5R104K6R3NTA+C0201X5R104K6R3NJA~~GRM033R60J104KE19D~~CC0201KRX5R5BB104  [C0201]  20.57 41.22 90 top
CB398  CL10A226MQ8NRNC~~GRM188R60J226MEA0D~~JDK107BBJ226MA-T~~CC0603MRX5R5BB226  [C0603_L]  23.17 41.24 90 bottom
CB399  CL10A226MQ8NRNC~~GRM188R60J226MEA0D~~JDK107BBJ226MA-T~~CC0603MRX5R5BB226  [C0603_L]  21.77 41.24 90 bottom
CB404  CL10A226MQ8NRNC~~GRM188R60J226MEA0D~~JDK107BBJ226MA-T~~CC0603MRX5R5BB226  [C0603_L]  24.64 41.22 90 top
CB413  C0201X5R104M6R3NTA~~0201X104M6R3NT  [C0201]  181.61 49.86 90 bottom
CB414  C0201X5R104K6R3NTA+C0201X5R104K6R3NJA~~GRM033R60J104KE19D~~CC0201KRX5R5BB104  [C0201]  116.84 4.52 0 bottom
CB415  CL10A226MQ8NRNC~~GRM188R60J226MEA0D~~JDK107BBJ226MA-T~~CC0603MRX5R5BB226  [C0603_L]  115.06 4.52 180 bottom
CD1  C0201X5R104M6R3NTA~~0201X104M6R3NT  [C0201]  57.1 83.89 270 bottom
CD2  C0201X5R104M6R3NTA~~0201X104M6R3NT  [C0201]  61.34 84.66 270 top
CD3  C0201X5R104M6R3NTA~~0201X104M6R3NT  [C0201]  64.64 88.97 180 top
CD4  C0201X5R104M6R3NTA~~0201X104M6R3NT  [C0201]  71.12 92.15 180 top
CD5  C0201X5R104M6R3NTA~~0201X104M6R3NT  [C0201]  64.01 83.64 90 top
CD6  C0201X5R104M6R3NTA~~0201X104M6R3NT  [C0201]  78.99 84.66 270 top
CD7  C0201X5R104M6R3NTA~~0201X104M6R3NT  [C0201]  82.29 88.97 180 top
CD8  C0201X5R104M6R3NTA~~0201X104M6R3NT  [C0201]  88.77 92.15 180 top
CD9  C0201X5R104M6R3NTA~~0201X104M6R3NT  [C0201]  81.66 83.51 90 top
CD10  C0201X5R104M6R3NTA~~0201X104M6R3NT  [C0201]  96.65 84.66 270 top
CD11  C0201X5R104M6R3NTA~~0201X104M6R3NT  [C0201]  99.57 89.48 180 top
CD12  C0201X5R104M6R3NTA~~0201X104M6R3NT  [C0201]  107.31 91.64 90 top
CD13  C0201X5R104M6R3NTA~~0201X104M6R3NT  [C0201]  98.8 84.66 90 top
CD14  C0201X5R104M6R3NTA~~0201X104M6R3NT  [C0201]  114.3 87.96 90 top
CD15  C0201X5R104M6R3NTA~~0201X104M6R3NT  [C0201]  117.6 89.48 180 top
CD16  C0201X5R104M6R3NTA~~0201X104M6R3NT  [C0201]  115.19 90.88 0 top
CD17  C0201X5R104M6R3NTA~~0201X104M6R3NT  [C0201]  116.46 84.02 0 top
CD18  C0201X5R105M6R3NTX~~CL03A105MQ3CSNH~~GRM033R60J105MEA2D~~JMK063ABJ105MP+JDK063ABJ105MP~~CC0201MRX5R5BB105  [C0201_0D4]  70.23 89.48 0 top
CD19  C0201X5R105M6R3NTX~~CL03A105MQ3CSNH~~GRM033R60J105MEA2D~~JMK063ABJ105MP+JDK063ABJ105MP~~CC0201MRX5R5BB105  [C0201_0D4]  69.72 78.81 270 top
CD20  C0201X5R105M6R3NTX~~CL03A105MQ3CSNH~~GRM033R60J105MEA2D~~JMK063ABJ105MP+JDK063ABJ105MP~~CC0201MRX5R5BB105  [C0201_0D4]  72.01 84.27 90 top
CD21  C0201X5R105M6R3NTX~~CL03A105MQ3CSNH~~GRM033R60J105MEA2D~~JMK063ABJ105MP+JDK063ABJ105MP~~CC0201MRX5R5BB105  [C0201_0D4]  70.23 83.13 0 top
CD22  C0201X5R105M6R3NTX~~CL03A105MQ3CSNH~~GRM033R60J105MEA2D~~JMK063ABJ105MP+JDK063ABJ105MP~~CC0201MRX5R5BB105  [C0201_0D4]  61.34 87.96 270 top
CD23  C0201X5R105M6R3NTX~~CL03A105MQ3CSNH~~GRM033R60J105MEA2D~~JMK063ABJ105MP+JDK063ABJ105MP~~CC0201MRX5R5BB105  [C0201_0D4]  67.94 82.37 180 top
CD24  C0201C0G120J250NTA~~GRM0335C1E120JA01D~~CC0201JRNPO8BN120  [C0201]  67.82 90.88 180 top
CD25  C0201C0G2R2C500NTA~~GRM0335C1H2R2CA01D~~CC0201CRNPO9BN2R2  [C0201]  72.01 88.21 270 top
CD26  C0402X5R106M6R3NTC~~CL05A106MQ5NUNC~~GRM155R60J106ME44~~JMK105CBJ106MV-F  [C0402_0D8]  66.67 84.02 270 top
CD27  C0402X5R106M6R3NTC~~CL05A106MQ5NUNC~~GRM155R60J106ME44~~JMK105CBJ106MV-F  [C0402_0D8]  66.67 87.83 270 top
CD28  C0201X5R105M6R3NTX~~CL03A105MQ3CSNH~~GRM033R60J105MEA2D~~JMK063ABJ105MP+JDK063ABJ105MP~~CC0201MRX5R5BB105  [C0201_0D4]  103.12 82.37 180 top
CD29  C0201X5R105M6R3NTX~~CL03A105MQ3CSNH~~GRM033R60J105MEA2D~~JMK063ABJ105MP+JDK063ABJ105MP~~CC0201MRX5R5BB105  [C0201_0D4]  107.31 84.4 90 top
CD30  C0201X5R105M6R3NTX~~CL03A105MQ3CSNH~~GRM033R60J105MEA2D~~JMK063ABJ105MP+JDK063ABJ105MP~~CC0201MRX5R5BB105  [C0201_0D4]  100.96 79.07 180 top
CD31  C0201X5R105M6R3NTX~~CL03A105MQ3CSNH~~GRM033R60J105MEA2D~~JMK063ABJ105MP+JDK063ABJ105MP~~CC0201MRX5R5BB105  [C0201_0D4]  105.54 83.13 0 top
CD32  C0201X5R105M6R3NTX~~CL03A105MQ3CSNH~~GRM033R60J105MEA2D~~JMK063ABJ105MP+JDK063ABJ105MP~~CC0201MRX5R5BB105  [C0201_0D4]  96.65 87.96 270 top
CD33  C0201X5R105M6R3NTX~~CL03A105MQ3CSNH~~GRM033R60J105MEA2D~~JMK063ABJ105MP+JDK063ABJ105MP~~CC0201MRX5R5BB105  [C0201_0D4]  101.98 90.12 270 top
CD34  C0201C0G120J250NTA~~GRM0335C1E120JA01D~~CC0201JRNPO8BN120  [C0201]  97.53 83.13 180 top
CD35  C0201C0G2R2C500NTA~~GRM0335C1H2R2CA01D~~CC0201CRNPO9BN2R2  [C0201]  106.81 88.21 180 top
CD36  C0402X5R106M6R3NTC~~CL05A106MQ5NUNC~~GRM155R60J106ME44~~JMK105CBJ106MV-F  [C0402_0D8]  101.98 88.59 90 top
CD37  C0402X5R106M6R3NTC~~CL05A106MQ5NUNC~~GRM155R60J106ME44~~JMK105CBJ106MV-F  [C0402_0D8]  101.98 84.02 270 top
CD38  C0201X5R105M6R3NTX~~CL03A105MQ3CSNH~~GRM033R60J105MEA2D~~JMK063ABJ105MP+JDK063ABJ105MP~~CC0201MRX5R5BB105  [C0201_0D4]  68.32 83.64 0 top
CD39  C0201X5R105M6R3NTX~~CL03A105MQ3CSNH~~GRM033R60J105MEA2D~~JMK063ABJ105MP+JDK063ABJ105MP~~CC0201MRX5R5BB105  [C0201_0D4]  64.51 83.64 270 top
CD40  C0201X5R105M6R3NTX~~CL03A105MQ3CSNH~~GRM033R60J105MEA2D~~JMK063ABJ105MP+JDK063ABJ105MP~~CC0201MRX5R5BB105  [C0201_0D4]  71.5 82.24 90 top
CD41  C0201X5R105M6R3NTX~~CL03A105MQ3CSNH~~GRM033R60J105MEA2D~~JMK063ABJ105MP+JDK063ABJ105MP~~CC0201MRX5R5BB105  [C0201_0D4]  71.5 90.12 270 top
CD42  C0402X5R106M6R3NTC~~CL05A106MQ5NUNC~~GRM155R60J106ME44~~JMK105CBJ106MV-F  [C0402_0D8]  69.09 88.21 270 top
CD43  C0402X5R106M6R3NTC~~CL05A106MQ5NUNC~~GRM155R60J106ME44~~JMK105CBJ106MV-F  [C0402_0D8]  60.15 89.84 270 top
CD44  C0201X5R105M6R3NTX~~CL03A105MQ3CSNH~~GRM033R60J105MEA2D~~JMK063ABJ105MP+JDK063ABJ105MP~~CC0201MRX5R5BB105  [C0201_0D4]  107.06 82.5 90 top
CD45  C0201X5R105M6R3NTX~~CL03A105MQ3CSNH~~GRM033R60J105MEA2D~~JMK063ABJ105MP+JDK063ABJ105MP~~CC0201MRX5R5BB105  [C0201_0D4]  99.82 82.5 90 top
CD46  C0201X5R105M6R3NTX~~CL03A105MQ3CSNH~~GRM033R60J105MEA2D~~JMK063ABJ105MP+JDK063ABJ105MP~~CC0201MRX5R5BB105  [C0201_0D4]  106.3 90.88 0 top
CD47  C0201X5R105M6R3NTX~~CL03A105MQ3CSNH~~GRM033R60J105MEA2D~~JMK063ABJ105MP+JDK063ABJ105MP~~CC0201MRX5R5BB105  [C0201_0D4]  103.63 83.64 0 top
CD48  C0402X5R106M6R3NTC~~CL05A106MQ5NUNC~~GRM155R60J106ME44~~JMK105CBJ106MV-F  [C0402_0D8]  96.52 89.86 270 top
CD49  C0402X5R106M6R3NTC~~CL05A106MQ5NUNC~~GRM155R60J106ME44~~JMK105CBJ106MV-F  [C0402_0D8]  104.39 88.47 270 top
CD50  C0201X5R105M6R3NTX~~CL03A105MQ3CSNH~~GRM033R60J105MEA2D~~JMK063ABJ105MP+JDK063ABJ105MP~~CC0201MRX5R5BB105  [C0201_0D4]  63.63 89.86 90 top
CD51  C0201X5R105M6R3NTX~~CL03A105MQ3CSNH~~GRM033R60J105MEA2D~~JMK063ABJ105MP+JDK063ABJ105MP~~CC0201MRX5R5BB105  [C0201_0D4]  69.72 80.08 270 top
CD52  C0201X5R105M6R3NTX~~CL03A105MQ3CSNH~~GRM033R60J105MEA2D~~JMK063ABJ105MP+JDK063ABJ105MP~~CC0201MRX5R5BB105  [C0201_0D4]  67.82 92.15 180 top
CD53  C0201X5R105M6R3NTX~~CL03A105MQ3CSNH~~GRM033R60J105MEA2D~~JMK063ABJ105MP+JDK063ABJ105MP~~CC0201MRX5R5BB105  [C0201_0D4]  63.63 92.4 90 top
CD54  C0201X5R105M6R3NTX~~CL03A105MQ3CSNH~~GRM033R60J105MEA2D~~JMK063ABJ105MP+JDK063ABJ105MP~~CC0201MRX5R5BB105  [C0201_0D4]  67.82 81.1 180 top
CD55  C0201X5R105M6R3NTX~~CL03A105MQ3CSNH~~GRM033R60J105MEA2D~~JMK063ABJ105MP+JDK063ABJ105MP~~CC0201MRX5R5BB105  [C0201_0D4]  70.99 80.46 0 top
CD56  C0402X5R106M6R3NTC~~CL05A106MQ5NUNC~~GRM155R60J106ME44~~JMK105CBJ106MV-F  [C0402_0D8]  66.67 79.96 270 top
CD57  C0402X5R106M6R3NTC~~CL05A106MQ5NUNC~~GRM155R60J106ME44~~JMK105CBJ106MV-F  [C0402_0D8]  66.55 91.13 270 top
CD58  C0201X5R105M6R3NTX~~CL03A105MQ3CSNH~~GRM033R60J105MEA2D~~JMK063ABJ105MP+JDK063ABJ105MP~~CC0201MRX5R5BB105  [C0201_0D4]  100.71 81.1 0 top
CD59  C0201X5R105M6R3NTX~~CL03A105MQ3CSNH~~GRM033R60J105MEA2D~~JMK063ABJ105MP+JDK063ABJ105MP~~CC0201MRX5R5BB105  [C0201_0D4]  104.01 90.88 180 top
CD60  C0201X5R105M6R3NTX~~CL03A105MQ3CSNH~~GRM033R60J105MEA2D~~JMK063ABJ105MP+JDK063ABJ105MP~~CC0201MRX5R5BB105  [C0201_0D4]  97.53 90.88 180 top
CD61  C0201X5R105M6R3NTX~~CL03A105MQ3CSNH~~GRM033R60J105MEA2D~~JMK063ABJ105MP+JDK063ABJ105MP~~CC0201MRX5R5BB105  [C0201_0D4]  98.04 80.08 270 top
CD62  C0201X5R105M6R3NTX~~CL03A105MQ3CSNH~~GRM033R60J105MEA2D~~JMK063ABJ105MP+JDK063ABJ105MP~~CC0201MRX5R5BB105  [C0201_0D4]  106.3 81.73 0 top
CD63  C0201X5R105M6R3NTX~~CL03A105MQ3CSNH~~GRM033R60J105MEA2D~~JMK063ABJ105MP+JDK063ABJ105MP~~CC0201MRX5R5BB105  [C0201_0D4]  103.12 81.1 180 top
CD64  C0402X5R106M6R3NTC~~CL05A106MQ5NUNC~~GRM155R60J106ME44~~JMK105CBJ106MV-F  [C0402_0D8]  101.98 91.64 270 top
CD65  C0402X5R106M6R3NTC~~CL05A106MQ5NUNC~~GRM155R60J106ME44~~JMK105CBJ106MV-F  [C0402_0D8]  103.63 79.32 270 top
CD66  C0201X5R105M6R3NTX~~CL03A105MQ3CSNH~~GRM033R60J105MEA2D~~JMK063ABJ105MP+JDK063ABJ105MP~~CC0201MRX5R5BB105  [C0201_0D4]  84.33 88.59 270 top
CD67  C0201X5R105M6R3NTX~~CL03A105MQ3CSNH~~GRM033R60J105MEA2D~~JMK063ABJ105MP+JDK063ABJ105MP~~CC0201MRX5R5BB105  [C0201_0D4]  89.66 84.27 90 top
CD68  C0201X5R105M6R3NTX~~CL03A105MQ3CSNH~~GRM033R60J105MEA2D~~JMK063ABJ105MP+JDK063ABJ105MP~~CC0201MRX5R5BB105  [C0201_0D4]  83.06 78.56 180 top
CD69  C0201X5R105M6R3NTX~~CL03A105MQ3CSNH~~GRM033R60J105MEA2D~~JMK063ABJ105MP+JDK063ABJ105MP~~CC0201MRX5R5BB105  [C0201_0D4]  78.99 87.96 270 top
CD70  C0201X5R105M6R3NTX~~CL03A105MQ3CSNH~~GRM033R60J105MEA2D~~JMK063ABJ105MP+JDK063ABJ105MP~~CC0201MRX5R5BB105  [C0201_0D4]  87.88 83.13 0 top
CD71  C0201X5R105M6R3NTX~~CL03A105MQ3CSNH~~GRM033R60J105MEA2D~~JMK063ABJ105MP+JDK063ABJ105MP~~CC0201MRX5R5BB105  [C0201_0D4]  87.88 89.48 0 top
CD72  C0201C0G120J250NTA~~GRM0335C1E120JA01D~~CC0201JRNPO8BN120  [C0201]  85.47 90.88 180 top
CD73  C0201C0G2R2C500NTA~~GRM0335C1H2R2CA01D~~CC0201CRNPO9BN2R2  [C0201]  89.66 88.21 270 top
CD74  C0402X5R106M6R3NTC~~CL05A106MQ5NUNC~~GRM155R60J106ME44~~JMK105CBJ106MV-F  [C0402_0D8]  84.33 84.02 270 top
CD75  C0201X5R105M6R3NTX~~CL03A105MQ3CSNH~~GRM033R60J105MEA2D~~JMK063ABJ105MP+JDK063ABJ105MP~~CC0201MRX5R5BB105  [C0201_0D4]  113.92 84.91 0 top
CD76  C0201X5R105M6R3NTX~~CL03A105MQ3CSNH~~GRM033R60J105MEA2D~~JMK063ABJ105MP+JDK063ABJ105MP~~CC0201MRX5R5BB105  [C0201_0D4]  117.98 79.45 270 top
CD77  C0201X5R105M6R3NTX~~CL03A105MQ3CSNH~~GRM033R60J105MEA2D~~JMK063ABJ105MP+JDK063ABJ105MP~~CC0201MRX5R5BB105  [C0201_0D4]  113.92 84.27 0 top
CD78  C0201X5R105M6R3NTX~~CL03A105MQ3CSNH~~GRM033R60J105MEA2D~~JMK063ABJ105MP+JDK063ABJ105MP~~CC0201MRX5R5BB105  [C0201_0D4]  124.46 88.34 180 top
CD79  C0201X5R105M6R3NTX~~CL03A105MQ3CSNH~~GRM033R60J105MEA2D~~JMK063ABJ105MP+JDK063ABJ105MP~~CC0201MRX5R5BB105  [C0201_0D4]  120.78 82.5 180 top
CD80  C0201X5R105M6R3NTX~~CL03A105MQ3CSNH~~GRM033R60J105MEA2D~~JMK063ABJ105MP+JDK063ABJ105MP~~CC0201MRX5R5BB105  [C0201_0D4]  119.63 87.96 90 top
CD81  C0201C0G120J250NTA~~GRM0335C1E120JA01D~~CC0201JRNPO8BN120  [C0201]  119.63 89.1 90 top
CD82  C0201C0G2R2C500NTA~~GRM0335C1H2R2CA01D~~CC0201CRNPO9BN2R2  [C0201]  124.46 84.27 180 top
CD83  C0402X5R106M6R3NTC~~CL05A106MQ5NUNC~~GRM155R60J106ME44~~JMK105CBJ106MV-F  [C0402_0D8]  119.63 84.02 270 top
CD84  C0201X5R105M6R3NTX~~CL03A105MQ3CSNH~~GRM033R60J105MEA2D~~JMK063ABJ105MP+JDK063ABJ105MP~~CC0201MRX5R5BB105  [C0201_0D4]  89.15 90.37 270 top
CD85  C0201X5R105M6R3NTX~~CL03A105MQ3CSNH~~GRM033R60J105MEA2D~~JMK063ABJ105MP+JDK063ABJ105MP~~CC0201MRX5R5BB105  [C0201_0D4]  85.98 83.64 0 top
CD86  C0201X5R105M6R3NTX~~CL03A105MQ3CSNH~~GRM033R60J105MEA2D~~JMK063ABJ105MP+JDK063ABJ105MP~~CC0201MRX5R5BB105  [C0201_0D4]  82.17 83.51 270 top
CD87  C0201X5R105M6R3NTX~~CL03A105MQ3CSNH~~GRM033R60J105MEA2D~~JMK063ABJ105MP+JDK063ABJ105MP~~CC0201MRX5R5BB105  [C0201_0D4]  89.15 82.24 90 top
CD88  C0402X5R106M6R3NTC~~CL05A106MQ5NUNC~~GRM155R60J106ME44~~JMK105CBJ106MV-F  [C0402_0D8]  86.74 88.21 270 top
CD89  C0201X5R105M6R3NTX~~CL03A105MQ3CSNH~~GRM033R60J105MEA2D~~JMK063ABJ105MP+JDK063ABJ105MP~~CC0201MRX5R5BB105  [C0201_0D4]  118.11 82.5 180 top
CD90  C0201X5R105M6R3NTX~~CL03A105MQ3CSNH~~GRM033R60J105MEA2D~~JMK063ABJ105MP+JDK063ABJ105MP~~CC0201MRX5R5BB105  [C0201_0D4]  122.05 88.34 90 top
CD91  C0201X5R105M6R3NTX~~CL03A105MQ3CSNH~~GRM033R60J105MEA2D~~JMK063ABJ105MP+JDK063ABJ105MP~~CC0201MRX5R5BB105  [C0201_0D4]  121.16 83.64 0 top
CD92  C0201X5R105M6R3NTX~~CL03A105MQ3CSNH~~GRM033R60J105MEA2D~~JMK063ABJ105MP+JDK063ABJ105MP~~CC0201MRX5R5BB105  [C0201_0D4]  114.55 82.62 180 top
CD93  C0402X5R106M6R3NTC~~CL05A106MQ5NUNC~~GRM155R60J106ME44~~JMK105CBJ106MV-F  [C0402_0D8]  113.41 90.12 90 top
CD94  C0201X5R105M6R3NTX~~CL03A105MQ3CSNH~~GRM033R60J105MEA2D~~JMK063ABJ105MP+JDK063ABJ105MP~~CC0201MRX5R5BB105  [C0201_0D4]  85.47 81.1 180 top
CD95  C0201X5R105M6R3NTX~~CL03A105MQ3CSNH~~GRM033R60J105MEA2D~~JMK063ABJ105MP+JDK063ABJ105MP~~CC0201MRX5R5BB105  [C0201_0D4]  85.47 92.15 180 top
CD96  C0201X5R105M6R3NTX~~CL03A105MQ3CSNH~~GRM033R60J105MEA2D~~JMK063ABJ105MP+JDK063ABJ105MP~~CC0201MRX5R5BB105  [C0201_0D4]  78.99 90.88 90 top
CD97  C0201X5R105M6R3NTX~~CL03A105MQ3CSNH~~GRM033R60J105MEA2D~~JMK063ABJ105MP+JDK063ABJ105MP~~CC0201MRX5R5BB105  [C0201_0D4]  81.66 80.08 270 top
CD98  C0201X5R105M6R3NTX~~CL03A105MQ3CSNH~~GRM033R60J105MEA2D~~JMK063ABJ105MP+JDK063ABJ105MP~~CC0201MRX5R5BB105  [C0201_0D4]  88.64 80.46 0 top
CD99  C0201X5R105M6R3NTX~~CL03A105MQ3CSNH~~GRM033R60J105MEA2D~~JMK063ABJ105MP+JDK063ABJ105MP~~CC0201MRX5R5BB105  [C0201_0D4]  81.28 89.86 90 top
CD100  C0402X5R106M6R3NTC~~CL05A106MQ5NUNC~~GRM155R60J106ME44~~JMK105CBJ106MV-F  [C0402_0D8]  84.33 79.96 270 top
CD101  C0201X5R105M6R3NTX~~CL03A105MQ3CSNH~~GRM033R60J105MEA2D~~JMK063ABJ105MP+JDK063ABJ105MP~~CC0201MRX5R5BB105  [C0201_0D4]  123.95 81.73 0 top
CD102  C0201X5R105M6R3NTX~~CL03A105MQ3CSNH~~GRM033R60J105MEA2D~~JMK063ABJ105MP+JDK063ABJ105MP~~CC0201MRX5R5BB105  [C0201_0D4]  120.78 81.1 180 top
CD103  C0201X5R105M6R3NTX~~CL03A105MQ3CSNH~~GRM033R60J105MEA2D~~JMK063ABJ105MP+JDK063ABJ105MP~~CC0201MRX5R5BB105  [C0201_0D4]  118.24 81.1 0 top
CD104  C0201X5R105M6R3NTX~~CL03A105MQ3CSNH~~GRM033R60J105MEA2D~~JMK063ABJ105MP+JDK063ABJ105MP~~CC0201MRX5R5BB105  [C0201_0D4]  116.58 80.85 270 top
CD105  C0201X5R105M6R3NTX~~CL03A105MQ3CSNH~~GRM033R60J105MEA2D~~JMK063ABJ105MP+JDK063ABJ105MP~~CC0201MRX5R5BB105  [C0201_0D4]  122.3 83 270 top
CD106  C0201X5R105M6R3NTX~~CL03A105MQ3CSNH~~GRM033R60J105MEA2D~~JMK063ABJ105MP+JDK063ABJ105MP~~CC0201MRX5R5BB105  [C0201_0D4]  122.81 92.63 180 top
CD107  C0402X5R106M6R3NTC~~CL05A106MQ5NUNC~~GRM155R60J106ME44~~JMK105CBJ106MV-F  [C0402_0D8]  119.63 90.88 270 top
CE7  C0603X5R106M250NTK~~CL10A106MA8NRNC~~GRM188R61E106MA73D~~TMK107BBJ106MA  [C0603_L]  176.07 10.44 180 top
CE8  CC0201KRX5R7BB104~~C0201X5R104M160NTA  [C0201]  176.28 9.52 180 top
CE9  CC0201KRX5R7BB104~~C0201X5R104M160NTA  [C0201]  183.66 11.83 0 top
CE14  CC0201KRX5R7BB104~~C0201X5R104M160NTA  [C0201]  143.51 20.39 0 bottom
CE18  C0201X5R104M6R3NTA~~0201X104M6R3NT  [C0201]  154.94 24.58 180 top
CE19  C0201X5R104M6R3NTA~~0201X104M6R3NT  [C0201]  188.87 16.74 0 top
CE20  C0201X5R104M6R3NTA~~0201X104M6R3NT  [C0201]  186.54 17.96 270 top
CE21  C0402X5R475M100NTC~~CL05A475MP5NRNC~~GRM155R61A475MEAA~~CC0402MRX5R6BB475~~LMK105BBJ475MVLF  [C0402_0D65]  186.74 20.24 90 top
CE22  CC0201KRX7R9BB152~~C0201X7R152K500NTA  [C0201]  186.69 14.78 0 top
CE23  C0201X5R105M6R3NTX~~CL03A105MQ3CSNH~~GRM033R60J105MEA2D~~JMK063ABJ105MP+JDK063ABJ105MP~~CC0201MRX5R5BB105  [C0201_0D4]  63.19 9.47 180 bottom
CE24  C0201X5R104M6R3NTA~~0201X104M6R3NT  [C0201]  63.19 9.98 180 bottom
CE25  C0201X5R105M6R3NTX~~CL03A105MQ3CSNH~~GRM033R60J105MEA2D~~JMK063ABJ105MP+JDK063ABJ105MP~~CC0201MRX5R5BB105  [C0201_0D4]  16.25 83 270 top
CE26  C0201X5R104M6R3NTA~~0201X104M6R3NT  [C0201]  169.06 21.66 0 top
CE32  C0201X5R104M6R3NTA~~0201X104M6R3NT  [C0201]  169.06 21.1 0 top
CE33  C0201X5R104M6R3NTA~~0201X104M6R3NT  [C0201]  156.36 22.78 270 top
CE34  C0201X5R104M6R3NTA~~0201X104M6R3NT  [C0201]  170.56 14.81 180 top
CE35  C0201X5R104M6R3NTA~~0201X104M6R3NT  [C0201]  154.94 23.95 180 top
CE36  C0201X5R104M6R3NTA~~0201X104M6R3NT  [C0201]  170.43 17.22 0 top
CE37  C0201X7R102K250NTA+C0201X7R102K250NJA~~GRM033R71E102KA01D~~CC0201KRX7R8BB102  [C0201]  170.43 17.73 0 top
CE38  C0201X5R104M6R3NTA~~0201X104M6R3NT  [C0201]  156.97 16.43 270 top
CE39  C0201X5R104M6R3NTA~~0201X104M6R3NT  [C0201]  154.94 22.81 270 top
CE40  C0201X5R105M6R3NTX~~CL03A105MQ3CSNH~~GRM033R60J105MEA2D~~JMK063ABJ105MP+JDK063ABJ105MP~~CC0201MRX5R5BB105  [C0201_0D4]  157.17 14.5 180 top
CE42  C0201X7R102K250NTA+C0201X7R102K250NJA~~GRM033R71E102KA01D~~CC0201KRX7R8BB102  [C0201]  165.76 12.29 270 top
CE43  C0201X5R104M6R3NTA~~0201X104M6R3NT  [C0201]  160.83 11.96 270 top
CE44  CAP  [C0201]  68.32 7.19 90 top
CE45  C0201C0G101J250NTA+C0201C0G101J250NJA~~GRM0335C1E101JD01D~~CC0201JRNPO8BN101  [C0201]  72.69 5.45 90 top
CE46  C0201X5R104M6R3NTA~~0201X104M6R3NT  [C0201]  169.06 20.55 0 top
CE52  C0201X5R104M6R3NTA~~0201X104M6R3NT  [C0201]  162.61 26.24 180 top
CE53  C0201X5R104M6R3NTA~~0201X104M6R3NT  [C0201]  162.61 26.87 180 top
CE54  C0201X7R472K100NTA+C0201X7R472K100NJA~~GRM033R71A472KA01D~~CC0201KRX7R6BB472  [C0201]  57.53 10.49 0 bottom
CE55  C0201X5R104M6R3NTA~~0201X104M6R3NT  [C0201]  55.5 9.85 90 bottom
CE373  CC0201KRX5R7BB104~~C0201X5R104M160NTA  [C0201]  158.21 6.63 270 top
CE374  C0201C0G101J500NTA~~GRM0335C1H101JA01D~~CC0201JRNPO9BN101  [C0201]  155.6 19.73 180 top
CE375  CAP  [C0201]  158.85 12.77 180 top
CE376  C0201X7R472K100NTA+C0201X7R472K100NJA~~GRM033R71A472KA01D~~CC0201KRX7R6BB472  [C0201]  157.17 13.99 180 top
CE377  C0201X7R472K100NTA+C0201X7R472K100NJA~~GRM033R71A472KA01D~~CC0201KRX7R6BB472  [C0201]  155.75 12.47 0 top
CE378  C0201X7R472K100NTA+C0201X7R472K100NJA~~GRM033R71A472KA01D~~CC0201KRX7R6BB472  [C0201]  157.17 19.02 0 top
CF1  CAP  [C0201_0D4]  138.94 34.67 90 top
CF2  CAP  [C0201]  137.92 34.67 90 top
CF3  CAP  [C0201]  138.81 26.11 270 top
CF8  CAP  [C0201]  138.43 34.67 90 top
CF9  cap  [C0201]  144.73 36.95 270 top
CF10  cap  [C0201]  133.22 28.14 0 top
CF11  CAP  [C0201_0D4]  135.38 34.74 90 top
CF12  cap  [C0201]  136.35 26.08 90 top
CHK1  EXC14CE900U  [EMI_0D85X0D65X0D5]  143.13 9.85 270 top
CHKB25  EXC14CE900U  [EMI_0D85X0D65X0D5]  22.61 37.09 270 top
CHKB26  ICMF052P120NFR  [NB_EMI4_0D64X0D57X0D38]  22.73 36.55 180 bottom
CHKB27  ICMF052P120NFR  [NB_EMI4_0D64X0D57X0D38]  22.73 37.92 180 bottom
CHKI1  EXC14CH350U  [EMI_0D85X0D65X0D5]  18.9 53.56 90 top
CHKI5  EXC14CH350U  [EMI_0D85X0D65X0D5]  18.9 50.77 90 top
CHKI6  EXC14CH350U  [EMI_0D85X0D65X0D5]  18.9 52.16 90 top
CHKI7  EXC14CH350U  [EMI_0D85X0D65X0D5]  18.9 55.06 90 top
CHKW1  EXC14CE900U  [EMI_0D85X0D65X0D5]  143.66 29.45 90 bottom
CHKX1  EXC14CH350U  [EMI_0D85X0D65X0D5]  32.58 72.82 0 bottom
CHKX2  EXC14CE900U  [EMI_0D85X0D65X0D5]  26.08 72.82 0 bottom
CHKX5  EXC14CE900U  [EMI_0D85X0D65X0D5]  24.43 72.26 0 bottom
CHKX6  EXC14CH350U  [EMI_0D85X0D65X0D5]  31.09 72.82 0 bottom
CHKX7  EXC14CH350U  [EMI_0D85X0D65X0D5]  29.61 72.82 0 bottom
CHKX8  EXC14CH350U  [EMI_0D85X0D65X0D5]  35.46 72.82 0 bottom
CHKX9  EXC14CH350U  [EMI_0D85X0D65X0D5]  34.03 72.82 0 bottom
CI1  LMK105BJ225MV-F~~CL05A225MP5NNNC~~GRM155R61A225ME95~~C0402X5R225M100NTB  [C0402_0D55]  20.32 60.47 90 bottom
CI20  C0603X5R106M6R3NTK~~CL10A106MQ8NNNC~~GRM188R60J106ME47D~~JMK107BJ106MA-T  [C0603_L]  21.54 60.53 90 bottom
CI61  C0201X5R104K100NTA~~GRM033R61A104KE15D~~CC0201KRX5R6BB104  [C0201]  29.34 51.13 0 top
CI62  C0201X5R104K100NTA~~GRM033R61A104KE15D~~CC0201KRX5R6BB104  [C0201]  29.34 50.62 0 top
CI63  C0201X5R104K100NTA~~GRM033R61A104KE15D~~CC0201KRX5R6BB104  [C0201]  29.34 52.89 0 top
CI64  C0201X5R104K100NTA~~GRM033R61A104KE15D~~CC0201KRX5R6BB104  [C0201]  29.34 52.38 0 top
CI65  C0201X5R104K100NTA~~GRM033R61A104KE15D~~CC0201KRX5R6BB104  [C0201]  29.34 54.09 0 top
CI66  C0201X5R104K100NTA~~GRM033R61A104KE15D~~CC0201KRX5R6BB104  [C0201]  29.34 53.58 0 top
CI67  C0201X5R104K100NTA~~GRM033R61A104KE15D~~CC0201KRX5R6BB104  [C0201]  29.34 55.29 0 top
CI68  C0201X5R104K100NTA~~GRM033R61A104KE15D~~CC0201KRX5R6BB104  [C0201]  29.34 54.78 0 top
CI103  C0201X5R474M6R3NTJ~~GRM033R60J474ME90D~~CC0201MRX5R5BB474  [C0201]  172.11 33.25 90 top
CI104  LMK105BJ225MV-F~~CL05A225MP5NNNC~~GRM155R61A225ME95~~C0402X5R225M100NTB  [C0402_0D55]  18.74 49.48 180 top
CI105  C0402X5R475M6R3NTC~~JMK105BBJ475MV-F+JDK105ABJ475MV~~CC0402MRX5R5BB475~~CL05A475MQ5NRNC~~GRM155R60J475ME87D  [C0402_0D65]  25.65 58.11 0 bottom
CI106  C0201X5R104K100NTA~~GRM033R61A104KE15D~~CC0201KRX5R6BB104  [C0201]  25.02 56.06 270 bottom
CI107  C0201X5R104K100NTA~~GRM033R61A104KE15D~~CC0201KRX5R6BB104  [C0201]  21.23 53.23 0 bottom
CI108  C0201X5R104K100NTA~~GRM033R61A104KE15D~~CC0201KRX5R6BB104  [C0201]  25.65 56.06 270 bottom
CI109  C0201X5R104K100NTA~~GRM033R61A104KE15D~~CC0201KRX5R6BB104  [C0201]  24.06 49.98 90 bottom
CI110  C0201X5R104K100NTA~~GRM033R61A104KE15D~~CC0201KRX5R6BB104  [C0201]  22.46 56.06 270 bottom
CI111  C0201X5R104K100NTA~~GRM033R61A104KE15D~~CC0201KRX5R6BB104  [C0201]  24.46 56.06 270 bottom
CI112  C0201X5R104K100NTA~~GRM033R61A104KE15D~~CC0201KRX5R6BB104  [C0201]  27.25 53.23 180 bottom
CI113  C0201X7R103K160NTA+C0201X7R103K160NJA~~GRM033R71C103KA01D~~CC0201KRX7R7BB103  [C0201]  26.29 56.06 90 bottom
CI114  C0201X7R103K160NTA+C0201X7R103K160NJA~~GRM033R71C103KA01D~~CC0201KRX7R7BB103  [C0201]  21.23 54.43 180 bottom
CI115  C0201X7R103K160NTA+C0201X7R103K160NJA~~GRM033R71C103KA01D~~CC0201KRX7R7BB103  [C0201]  20.83 50.75 270 bottom
CI116  C0201X5R104K100NTA~~GRM033R61A104KE15D~~CC0201KRX5R6BB104  [C0201]  21.33 50.75 90 bottom
CI117  C0201C0G3R3C250NTA~~CC0201CRNPO9BN3R3  [C0201]  17.93 55.03 270 top
CI118  C0201X5R104K100NTA~~GRM033R61A104KE15D~~CC0201KRX5R6BB104  [C0201]  21.84 50.75 90 bottom
CI119  C0201X7R103K160NTA+C0201X7R103K160NJA~~GRM033R71C103KA01D~~CC0201KRX7R7BB103  [C0201]  27.25 54.43 0 bottom
CI120  C0201X5R105M6R3NTX~~CL03A105MQ3CSNH~~GRM033R60J105MEA2D~~JMK063ABJ105MP+JDK063ABJ105MP~~CC0201MRX5R5BB105  [C0201_0D4]  26.8 47.95 270 top
CL1  cap  [C0201_0D4]  159.7 28.17 90 top
CL32  C0201X5R104M250NTJ  [C0201]  156.61 28.17 90 top
CL33  C0201X5R104M250NTJ  [C0201]  15.24 13.79 0 bottom
CLKO1  40MIL  [TPAD40-OP]  132.54 10.94 90 top
CN1  C0201C0G470J250NTA~~GRM0335C1E470JD01D~~CC0201JRNPO8BN470  [C0201]  21.69 3.78 90 top
CN2  C0201X5R224M6R3NTJ~~GRM033R60J224ME15D~~CC0201MRX5R5BB224  [C0201]  33.63 11.2 270 bottom
CN3  C0201X5R224M6R3NTJ~~GRM033R60J224ME15D~~CC0201MRX5R5BB224  [C0201]  33.12 11.2 270 bottom
CN4  CL10A226MQ8NRNC~~GRM188R60J226MEA0D~~JDK107BBJ226MA-T~~CC0603MRX5R5BB226  [C0603_L]  17.68 6.22 90 top
CN5  C0201X5R105M6R3NTX~~CL03A105MQ3CSNH~~GRM033R60J105MEA2D~~JMK063ABJ105MP+JDK063ABJ105MP~~CC0201MRX5R5BB105  [C0201_0D4]  35.3 3.73 90 top
CN6  C0201X5R104M6R3NTA~~0201X104M6R3NT  [C0201]  32.66 3.73 90 top
CN7  C0201C0G101J250NTA+C0201C0G101J250NJA~~GRM0335C1E101JD01D~~CC0201JRNPO8BN101  [C0201]  20.57 4.09 0 top
CN8  C0201X5R224M6R3NTJ~~GRM033R60J224ME15D~~CC0201MRX5R5BB224  [C0201]  31.6 11.71 270 bottom
CN9  C0201X5R224M6R3NTJ~~GRM033R60J224ME15D~~CC0201MRX5R5BB224  [C0201]  31.09 11.71 270 bottom
CN10  C0201X5R224M6R3NTJ~~GRM033R60J224ME15D~~CC0201MRX5R5BB224  [C0201]  28.5 11.5 270 bottom
CN11  C0201X5R224M6R3NTJ~~GRM033R60J224ME15D~~CC0201MRX5R5BB224  [C0201]  27.99 11.5 270 bottom
CN12  C0201X5R224M6R3NTJ~~GRM033R60J224ME15D~~CC0201MRX5R5BB224  [C0201]  26.36 12.11 270 bottom
CN13  C0201X5R224M6R3NTJ~~GRM033R60J224ME15D~~CC0201MRX5R5BB224  [C0201]  25.86 12.11 270 bottom
CN15  CL10A226MQ8NRNC~~GRM188R60J226MEA0D~~JDK107BBJ226MA-T~~CC0603MRX5R5BB226  [C0603_L]  19.05 6.22 90 top
CN16  C0201X5R105M6R3NTX~~CL03A105MQ3CSNH~~GRM033R60J105MEA2D~~JMK063ABJ105MP+JDK063ABJ105MP~~CC0201MRX5R5BB105  [C0201_0D4]  34.64 3.73 90 top
CN17  C0201X5R104M6R3NTA~~0201X104M6R3NT  [C0201]  33.98 3.73 90 top
CN18  C0201C0G101J250NTA+C0201C0G101J250NJA~~GRM0335C1E101JD01D~~CC0201JRNPO8BN101  [C0201]  33.32 3.73 90 top
CN19  C0201C0G470J250NTA~~GRM0335C1E470JD01D~~CC0201JRNPO8BN470  [C0201]  20.57 4.65 0 top
CO1  C0201X5R104M6R3NTA~~0201X104M6R3NT  [C0201]  133.96 7.49 0 top
CO2  C0201X5R104M6R3NTA~~0201X104M6R3NT  [C0201]  133.96 8.05 0 top
CP1  C0201X5R105M6R3NTX~~CL03A105MQ3CSNH~~GRM033R60J105MEA2D~~JMK063ABJ105MP+JDK063ABJ105MP~~CC0201MRX5R5BB105  [C0201_0D4]  143.64 7.67 180 top
CP2  C0201X5R104M6R3NTA~~0201X104M6R3NT  [C0201]  143.64 7.06 180 top
CP3  C0201X5R104M6R3NTA~~0201X104M6R3NT  [C0201]  133.96 8.61 0 top
CPU_BOSS1  4.5*2.9-M2  [HOLE_3D5_5_T]  56.38 68.23 180 bottom
CPU_BOSS2  4.5*2.9-M2  [HOLE_3D5_5_T]  122.38 68.23 180 bottom
CPU_BOSS3  4.5*2.9-M2  [HOLE_3D5_5_T]  56.38 37.97 180 bottom
CPU_BOSS4  4.5*2.9-M2  [HOLE_3D5_5_T]  122.38 37.97 180 bottom
CS1  C0201X5R104M6R3NTA~~0201X104M6R3NT  [C0201]  68.98 9.45 0 bottom
CS2  C0201C0G101J250NTA+C0201C0G101J250NJA~~GRM0335C1E101JD01D~~CC0201JRNPO8BN101  [C0201]  75.03 6.02 0 bottom
CS3  C0201X5R104M6R3NTA~~0201X104M6R3NT  [C0201]  151.38 8.71 180 bottom
CS17  C0201C0G101J250NTA+C0201C0G101J250NJA~~GRM0335C1E101JD01D~~CC0201JRNPO8BN101  [C0201]  76.3 6.02 0 bottom
CSO1  40MIL  [TPAD40-OP]  129.33 9.07 90 top
CT1  C0402X5R106M6R3NTC~~CL05A106MQ5NUNC~~GRM155R60J106ME44~~JMK105CBJ106MV-F  [C0402_0D8]  50.54 35.51 270 bottom
CT2  CC0201KRX5R7BB104~~C0201X5R104M160NTA  [C0201]  49.78 35.71 270 bottom
CT3  CL05A225MQ5NNNC~~GRM155R60J225ME15D~~JMK105 BJ225MV-F~~CC0402MRX5R5BB225~~C0402X5R225M6R3NTB  [C0402]  41.53 42.49 90 bottom
CT4  CC0201KRX5R7BB104~~C0201X5R104M160NTA  [C0201]  42.92 42.36 90 bottom
CT5  CC0201KRX5R7BB104~~C0201X5R104M160NTA  [C0201]  42.29 42.36 90 bottom
CT6  CL05A225MQ5NNNC~~GRM155R60J225ME15D~~JMK105 BJ225MV-F~~CC0402MRX5R5BB225~~C0402X5R225M6R3NTB  [C0402]  40.69 31.87 180 top
CT7  CC0201KRX5R7BB104~~C0201X5R104M160NTA  [C0201]  41.78 32.33 270 bottom
CT8  C0201X5R105M6R3NTX~~CL03A105MQ3CSNH~~GRM033R60J105MEA2D~~JMK063ABJ105MP+JDK063ABJ105MP~~CC0201MRX5R5BB105  [C0201_0D4]  44.07 42.36 270 bottom
CT9  CC0201KRX5R7BB104~~C0201X5R104M160NTA  [C0201]  50.67 33.47 0 bottom
CT10  C0201C0G100J250NTA~~GRM0335C1E100JA01D~~CC0201JRNPO8BN100  [C0201]  43.43 33.22 180 bottom
CT11  C0201C0G100J250NTA~~GRM0335C1E100JA01D~~CC0201JRNPO8BN100  [C0201]  44.96 33.09 0 bottom
CT12  C0201C0G100J250NTA~~GRM0335C1E100JA01D~~CC0201JRNPO8BN100  [C0201]  50.16 39.16 0 bottom
CT13  C0201C0G100J250NTA~~GRM0335C1E100JA01D~~CC0201JRNPO8BN100  [C0201]  50.16 38.61 0 bottom
CT14  C0201X5R104M250NTJ  [C0201]  50.16 42.49 0 bottom
CT15  C0201X5R104M250NTJ  [C0201]  50.16 41.96 0 bottom
CT16  cap  [C0201]  50.67 34.11 0 bottom
CT17  cap  [C0201]  50.16 36.65 0 bottom
CT18  C0201X5R224M6R3NTJ~~GRM033R60J224ME15D~~CC0201MRX5R5BB224  [C0201]  31.37 23.44 180 top
CT19  C0201X5R224M6R3NTJ~~GRM033R60J224ME15D~~CC0201MRX5R5BB224  [C0201]  31.37 23.95 180 top
CT20  C0201X5R224M6R3NTJ~~GRM033R60J224ME15D~~CC0201MRX5R5BB224  [C0201]  31.37 22.43 180 top
CT21  C0201X5R224M6R3NTJ~~GRM033R60J224ME15D~~CC0201MRX5R5BB224  [C0201]  31.37 22.93 180 top
CT22  C0201X5R224M6R3NTJ~~GRM033R60J224ME15D~~CC0201MRX5R5BB224  [C0201]  31.37 20.9 180 top
CT23  C0201X5R224M6R3NTJ~~GRM033R60J224ME15D~~CC0201MRX5R5BB224  [C0201]  31.37 20.39 180 top
CT24  C0201X5R224M6R3NTJ~~GRM033R60J224ME15D~~CC0201MRX5R5BB224  [C0201]  31.37 21.92 180 top
CT25  C0201X5R224M6R3NTJ~~GRM033R60J224ME15D~~CC0201MRX5R5BB224  [C0201]  31.37 21.41 180 top
CT26  C0201C0G100J250NTA~~GRM0335C1E100JA01D~~CC0201JRNPO8BN100  [C0201]  24.89 21.16 270 bottom
CT27  C0201C0G100J250NTA~~GRM0335C1E100JA01D~~CC0201JRNPO8BN100  [C0201]  24.13 21.16 270 bottom
